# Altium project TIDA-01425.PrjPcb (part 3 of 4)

## Sheet DDR3.schdoc: DDR3
size 431 x 279 mm; Date: Not shown in title block; ApprovedBy: Not shown in title block; CheckedBy: Not shown in title block; Author: Not shown in title block; CompanyName: Not shown in title block; DrawnBy: Donovan Porter; Engineer: Not shown in title block; Organization: Not shown in title block; Address1: Not shown in title block; Address2: Not shown in title block; Address3: Not shown in title block; Address4: Not shown in title block; DocumentNumber: 6; Revision: Use project parameter SCH_Rev; SheetNumber: 6; SheetTotal: 12; PageSetup: Record=PageOptions¦CenterHorizontal=True¦CenterVertical=True¦PrintScale=1.00¦XCorrection=1.00¦YCorrection=1.00¦PrintKind=0¦BorderSize=5000000¦LeftOffset=0¦BottomOffset=0¦Orientation=2¦PaperLength=1000¦PaperWidth=1000¦Scale=100¦PaperSource=15¦PrintQuality=600¦MediaType=1¦DitherType=10¦PaperKind=Letter¦PrintScaleMode=1
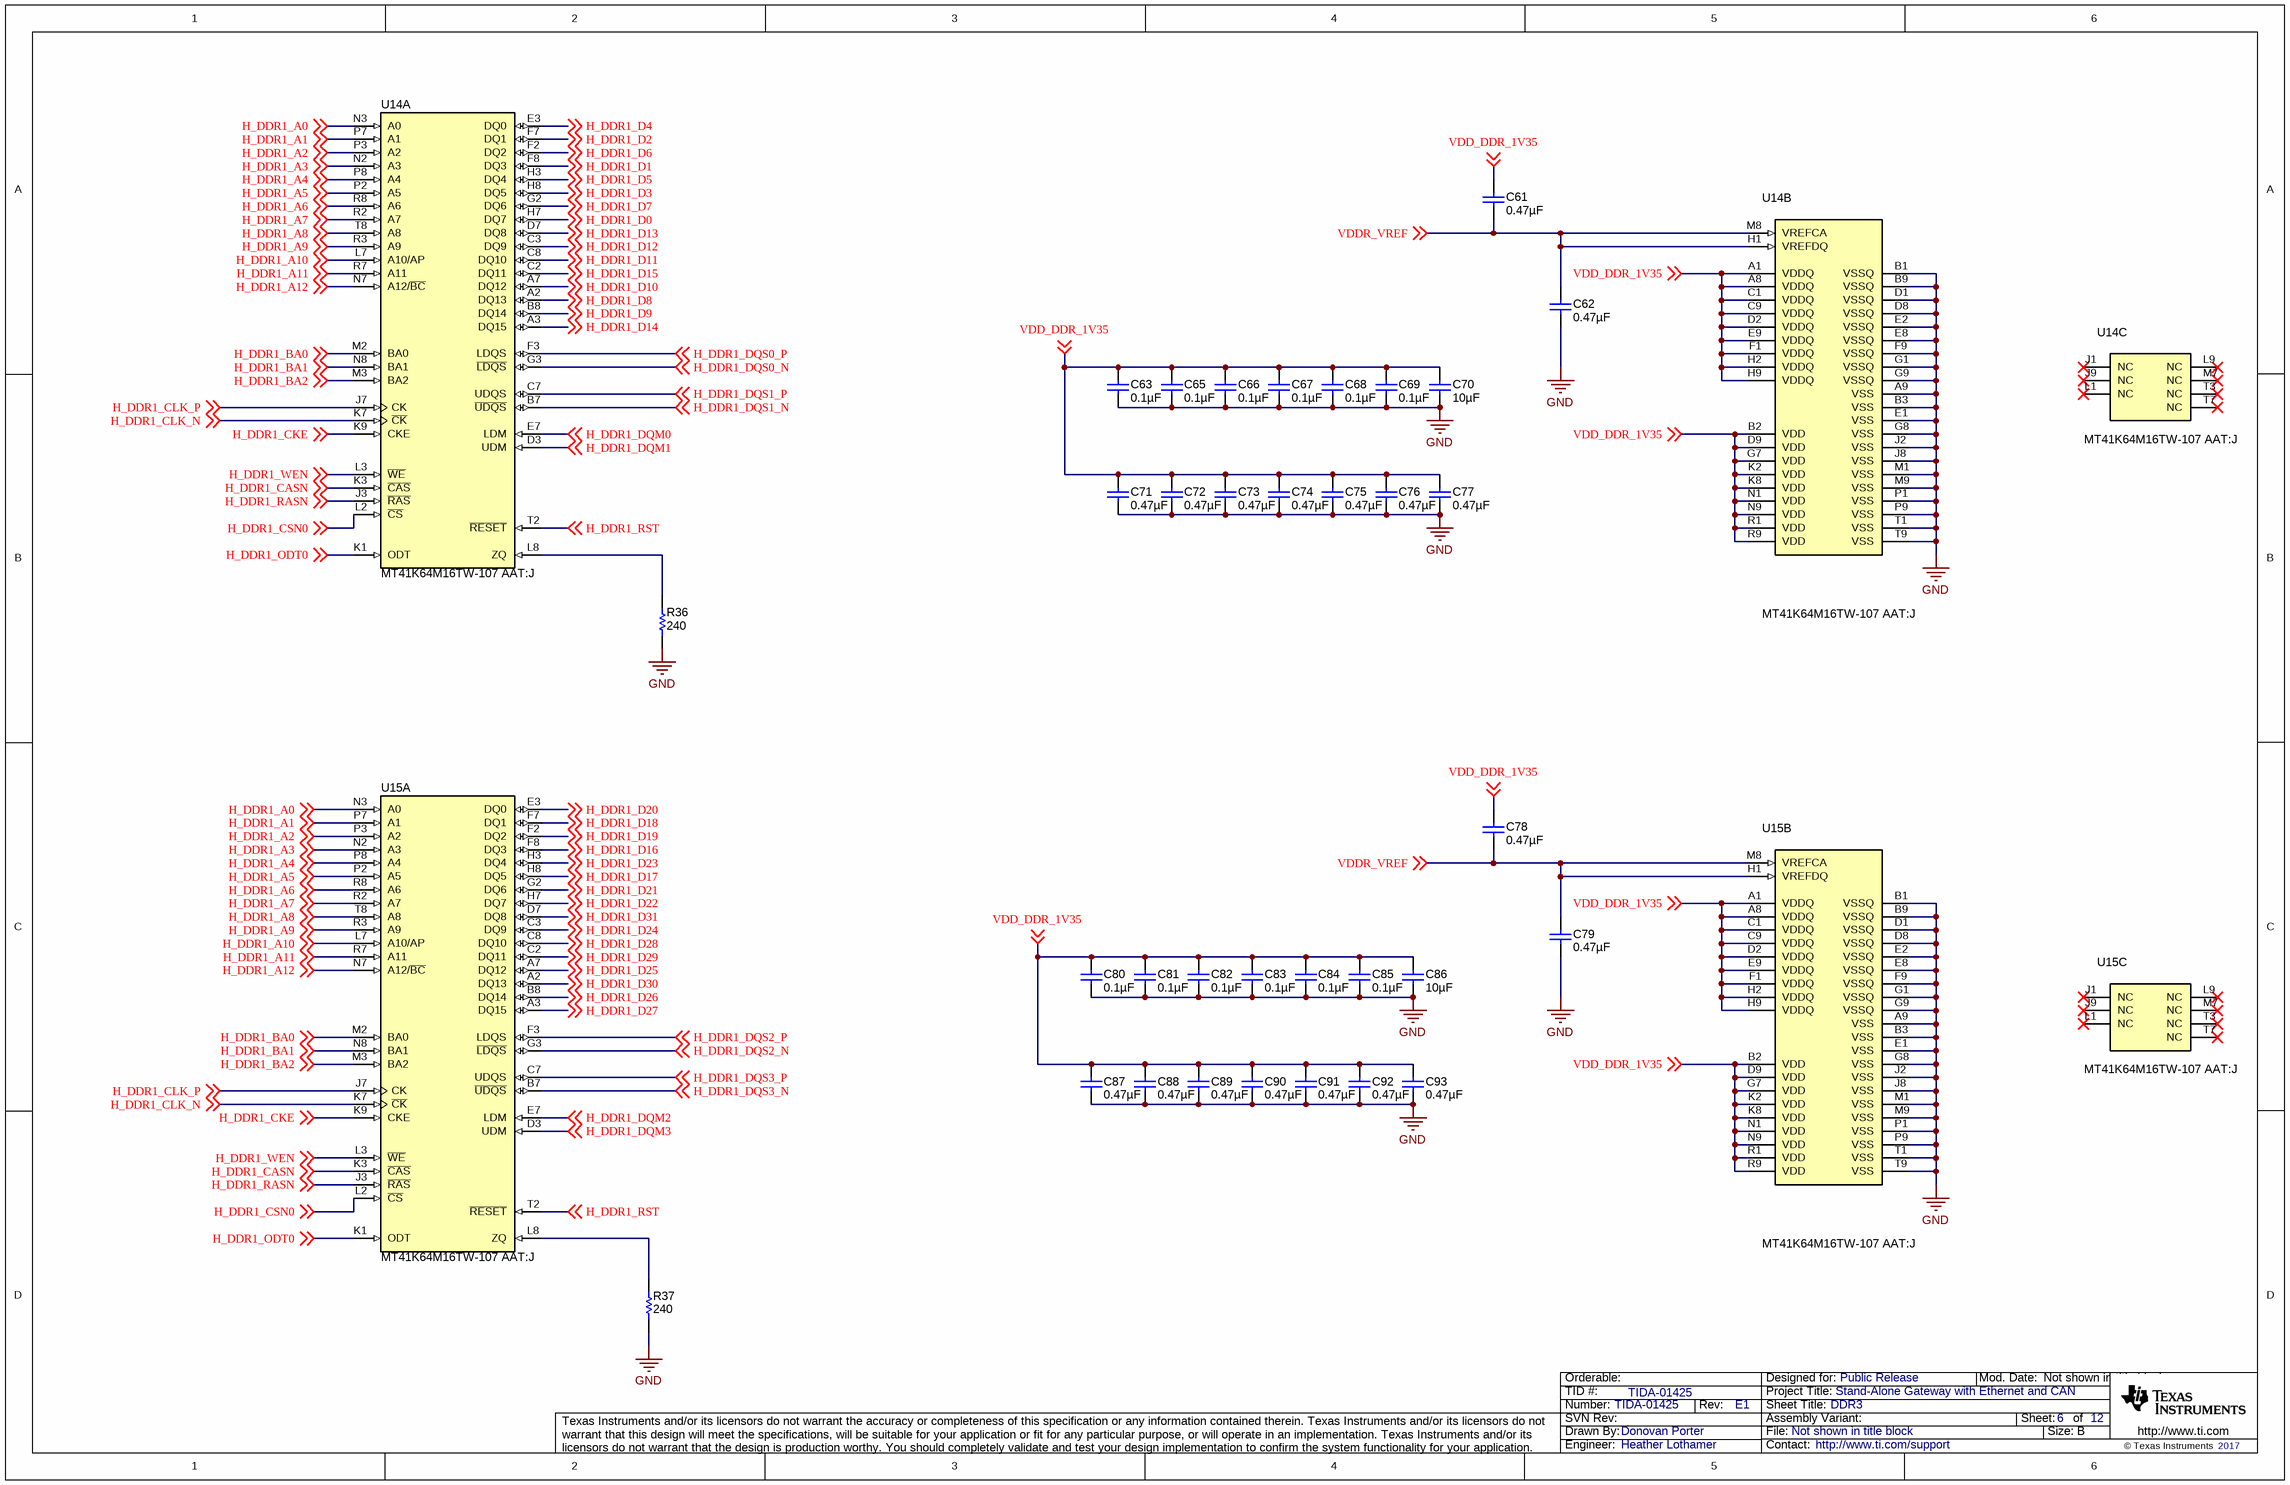
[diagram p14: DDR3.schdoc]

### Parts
C61  ValueDisplayed: 0.47µF  [0402L]  (hidden comment: GCM155C71A474KE36D)
C62  ValueDisplayed: 0.47µF  [0402L]  (hidden comment: GCM155C71A474KE36D)
C63  ValueDisplayed: 0.1µF  [0402L]  (hidden comment: GCM155R71C104KA55D)
C65  ValueDisplayed: 0.1µF  [0402L]  (hidden comment: GCM155R71C104KA55D)
C66  ValueDisplayed: 0.1µF  [0402L]  (hidden comment: GCM155R71C104KA55D)
C67  ValueDisplayed: 0.1µF  [0402L]  (hidden comment: GCM155R71C104KA55D)
C68  ValueDisplayed: 0.1µF  [0402L]  (hidden comment: GCM155R71C104KA55D)
C69  ValueDisplayed: 0.1µF  [0402L]  (hidden comment: GCM155R71C104KA55D)
C70  ValueDisplayed: 10µF  [0805_HV]  (hidden comment: LMK212BJ106KG-T)
C71  ValueDisplayed: 0.47µF  [0402L]  (hidden comment: GCM155C71A474KE36D)
C72  ValueDisplayed: 0.47µF  [0402L]  (hidden comment: GCM155C71A474KE36D)
C73  ValueDisplayed: 0.47µF  [0402L]  (hidden comment: GCM155C71A474KE36D)
C74  ValueDisplayed: 0.47µF  [0402L]  (hidden comment: GCM155C71A474KE36D)
C75  ValueDisplayed: 0.47µF  [0402L]  (hidden comment: GCM155C71A474KE36D)
C76  ValueDisplayed: 0.47µF  [0402L]  (hidden comment: GCM155C71A474KE36D)
C77  ValueDisplayed: 0.47µF  [0402L]  (hidden comment: GCM155C71A474KE36D)
C78  ValueDisplayed: 0.47µF  [0402L]  (hidden comment: GCM155C71A474KE36D)
C79  ValueDisplayed: 0.47µF  [0402L]  (hidden comment: GCM155C71A474KE36D)
C80  ValueDisplayed: 0.1µF  [0402L]  (hidden comment: GCM155R71C104KA55D)
C81  ValueDisplayed: 0.1µF  [0402L]  (hidden comment: GCM155R71C104KA55D)
C82  ValueDisplayed: 0.1µF  [0402L]  (hidden comment: GCM155R71C104KA55D)
C83  ValueDisplayed: 0.1µF  [0402L]  (hidden comment: GCM155R71C104KA55D)
C84  ValueDisplayed: 0.1µF  [0402L]  (hidden comment: GCM155R71C104KA55D)
C85  ValueDisplayed: 0.1µF  [0402L]  (hidden comment: GCM155R71C104KA55D)
C86  ValueDisplayed: 10µF  [0805_HV]  (hidden comment: LMK212BJ106KG-T)
C87  ValueDisplayed: 0.47µF  [0402L]  (hidden comment: GCM155C71A474KE36D)
C88  ValueDisplayed: 0.47µF  [0402L]  (hidden comment: GCM155C71A474KE36D)
C89  ValueDisplayed: 0.47µF  [0402L]  (hidden comment: GCM155C71A474KE36D)
C90  ValueDisplayed: 0.47µF  [0402L]  (hidden comment: GCM155C71A474KE36D)
C91  ValueDisplayed: 0.47µF  [0402L]  (hidden comment: GCM155C71A474KE36D)
C92  ValueDisplayed: 0.47µF  [0402L]  (hidden comment: GCM155C71A474KE36D)
C93  ValueDisplayed: 0.47µF  [0402L]  (hidden comment: GCM155C71A474KE36D)
R36  ValueDisplayed: 240  [0402]  (hidden comment: ERJ-2RKF2400X)
R37  ValueDisplayed: 240  [0402]  (hidden comment: ERJ-2RKF2400X)
U14  MT41K64M16TW-107 AAT:J  [96-FBGA]  (parts A,B,C of 3)
U15  MT41K64M16TW-107 AAT:J  [96-FBGA]  (parts A,B,C of 3)

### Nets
GND: C62.2 C63.2 C65.2 C66.2 C67.2 C68.2 C69.2 C70.2 C71.2 C72.2 C73.2 C74.2 C75.2 C76.2 C77.2 C79.2 C80.2 C81.2 C82.2 C83.2 C84.2 C85.2 C86.2 C87.2 C88.2 C89.2 C90.2 C91.2 C92.2 C93.2 R36.1 R37.1 U14.A9(VSS) U14.B1(VSSQ) U14.B3(VSS) U14.B9(VSSQ) U14.D1(VSSQ) U14.D8(VSSQ) U14.E1(VSS) U14.E2(VSSQ) U14.E8(VSSQ) U14.F9(VSSQ) U14.G1(VSSQ) U14.G8(VSS) U14.G9(VSSQ) U14.J2(VSS) U14.J8(VSS) U14.M1(VSS) U14.M9(VSS) U14.P1(VSS) U14.P9(VSS) U14.T1(VSS) U14.T9(VSS) U15.A9(VSS) U15.B1(VSSQ) U15.B3(VSS) U15.B9(VSSQ) U15.D1(VSSQ) U15.D8(VSSQ) U15.E1(VSS) U15.E2(VSSQ) U15.E8(VSSQ) U15.F9(VSSQ) U15.G1(VSSQ) U15.G8(VSS) U15.G9(VSSQ) U15.J2(VSS) U15.J8(VSS) U15.M1(VSS) U15.M9(VSS) U15.P1(VSS) U15.P9(VSS) U15.T1(VSS) U15.T9(VSS)
H_DDR1_A0: U14.N3(A0) U15.N3(A0) ; off-sheet H_DDR1_A0
H_DDR1_A1: U14.P7(A1) U15.P7(A1) ; off-sheet H_DDR1_A1
H_DDR1_A2: U14.P3(A2) U15.P3(A2) ; off-sheet H_DDR1_A2
H_DDR1_A3: U14.N2(A3) U15.N2(A3) ; off-sheet H_DDR1_A3
H_DDR1_A4: U14.P8(A4) U15.P8(A4) ; off-sheet H_DDR1_A4
H_DDR1_A5: U14.P2(A5) U15.P2(A5) ; off-sheet H_DDR1_A5
H_DDR1_A6: U14.R8(A6) U15.R8(A6) ; off-sheet H_DDR1_A6
H_DDR1_A7: U14.R2(A7) U15.R2(A7) ; off-sheet H_DDR1_A7
H_DDR1_A8: U14.T8(A8) U15.T8(A8) ; off-sheet H_DDR1_A8
H_DDR1_A9: U14.R3(A9) U15.R3(A9) ; off-sheet H_DDR1_A9
H_DDR1_A10: U14.L7(A10/AP) U15.L7(A10/AP) ; off-sheet H_DDR1_A10
H_DDR1_A11: U14.R7(A11) U15.R7(A11) ; off-sheet H_DDR1_A11
H_DDR1_A12: U14.N7(A12/~{BC}) U15.N7(A12/~{BC}) ; off-sheet H_DDR1_A12
H_DDR1_BA0: U14.M2(BA0) U15.M2(BA0) ; off-sheet H_DDR1_BA0
H_DDR1_BA1: U14.N8(BA1) U15.N8(BA1) ; off-sheet H_DDR1_BA1
H_DDR1_BA2: U14.M3(BA2) U15.M3(BA2) ; off-sheet H_DDR1_BA2
H_DDR1_CASN: U14.K3(~{CAS}) U15.K3(~{CAS}) ; off-sheet H_DDR1_CASN
H_DDR1_CKE: U14.K9(CKE) U15.K9(CKE) ; off-sheet H_DDR1_CKE
H_DDR1_CLK_N: U14.K7(~{CK}) U15.K7(~{CK}) ; off-sheet H_DDR1_CLK_N
H_DDR1_CLK_P: U14.J7(CK) U15.J7(CK) ; off-sheet H_DDR1_CLK_P
H_DDR1_CSN0: U14.L2(~{CS}) U15.L2(~{CS}) ; off-sheet H_DDR1_CSN0
H_DDR1_D0: U14.H7(DQ7) ; off-sheet H_DDR1_D0
H_DDR1_D1: U14.F8(DQ3) ; off-sheet H_DDR1_D1
H_DDR1_D2: U14.F7(DQ1) ; off-sheet H_DDR1_D2
H_DDR1_D3: U14.H8(DQ5) ; off-sheet H_DDR1_D3
H_DDR1_D4: U14.E3(DQ0) ; off-sheet H_DDR1_D4
H_DDR1_D5: U14.H3(DQ4) ; off-sheet H_DDR1_D5
H_DDR1_D6: U14.F2(DQ2) ; off-sheet H_DDR1_D6
H_DDR1_D7: U14.G2(DQ6) ; off-sheet H_DDR1_D7
H_DDR1_D8: U14.A2(DQ13) ; off-sheet H_DDR1_D8
H_DDR1_D9: U14.B8(DQ14) ; off-sheet H_DDR1_D9
H_DDR1_D10: U14.A7(DQ12) ; off-sheet H_DDR1_D10
H_DDR1_D11: U14.C8(DQ10) ; off-sheet H_DDR1_D11
H_DDR1_D12: U14.C3(DQ9) ; off-sheet H_DDR1_D12
H_DDR1_D13: U14.D7(DQ8) ; off-sheet H_DDR1_D13
H_DDR1_D14: U14.A3(DQ15) ; off-sheet H_DDR1_D14
H_DDR1_D15: U14.C2(DQ11) ; off-sheet H_DDR1_D15
H_DDR1_D16: U15.F8(DQ3) ; off-sheet H_DDR1_D16
H_DDR1_D17: U15.H8(DQ5) ; off-sheet H_DDR1_D17
H_DDR1_D18: U15.F7(DQ1) ; off-sheet H_DDR1_D18
H_DDR1_D19: U15.F2(DQ2) ; off-sheet H_DDR1_D19
H_DDR1_D20: U15.E3(DQ0) ; off-sheet H_DDR1_D20
H_DDR1_D21: U15.G2(DQ6) ; off-sheet H_DDR1_D21
H_DDR1_D22: U15.H7(DQ7) ; off-sheet H_DDR1_D22
H_DDR1_D23: U15.H3(DQ4) ; off-sheet H_DDR1_D23
H_DDR1_D24: U15.C3(DQ9) ; off-sheet H_DDR1_D24
H_DDR1_D25: U15.A7(DQ12) ; off-sheet H_DDR1_D25
H_DDR1_D26: U15.B8(DQ14) ; off-sheet H_DDR1_D26
H_DDR1_D27: U15.A3(DQ15) ; off-sheet H_DDR1_D27
H_DDR1_D28: U15.C8(DQ10) ; off-sheet H_DDR1_D28
H_DDR1_D29: U15.C2(DQ11) ; off-sheet H_DDR1_D29
H_DDR1_D30: U15.A2(DQ13) ; off-sheet H_DDR1_D30
H_DDR1_D31: U15.D7(DQ8) ; off-sheet H_DDR1_D31
H_DDR1_DQM0: U14.E7(LDM) ; off-sheet H_DDR1_DQM0
H_DDR1_DQM1: U14.D3(UDM) ; off-sheet H_DDR1_DQM1
H_DDR1_DQM2: U15.E7(LDM) ; off-sheet H_DDR1_DQM2
H_DDR1_DQM3: U15.D3(UDM) ; off-sheet H_DDR1_DQM3
H_DDR1_DQS0_N: U14.G3(~{LDQS}) ; off-sheet H_DDR1_DQS0_N
H_DDR1_DQS0_P: U14.F3(LDQS) ; off-sheet H_DDR1_DQS0_P
H_DDR1_DQS1_N: U14.B7(~{UDQS}) ; off-sheet H_DDR1_DQS1_N
H_DDR1_DQS1_P: U14.C7(UDQS) ; off-sheet H_DDR1_DQS1_P
H_DDR1_DQS2_N: U15.G3(~{LDQS}) ; off-sheet H_DDR1_DQS2_N
H_DDR1_DQS2_P: U15.F3(LDQS) ; off-sheet H_DDR1_DQS2_P
H_DDR1_DQS3_N: U15.B7(~{UDQS}) ; off-sheet H_DDR1_DQS3_N
H_DDR1_DQS3_P: U15.C7(UDQS) ; off-sheet H_DDR1_DQS3_P
H_DDR1_ODT0: U14.K1(ODT) U15.K1(ODT) ; off-sheet H_DDR1_ODT0
H_DDR1_RASN: U14.J3(~{RAS}) U15.J3(~{RAS}) ; off-sheet H_DDR1_RASN
H_DDR1_RST: U14.T2(~{RESET}) U15.T2(~{RESET}) ; off-sheet H_DDR1_RST
H_DDR1_WEN: U14.L3(~{WE}) U15.L3(~{WE}) ; off-sheet H_DDR1_WEN
VDD_DDR_1V35: C61.1 C63.1 C65.1 C66.1 C67.1 C68.1 C69.1 C70.1 C71.1 C72.1 C73.1 C74.1 C75.1 C76.1 C77.1 C78.1 C80.1 C81.1 C82.1 C83.1 C84.1 C85.1 C86.1 C87.1 C88.1 C89.1 C90.1 C91.1 C92.1 C93.1 U14.A1(VDDQ) U14.A8(VDDQ) U14.B2(VDD) U14.C1(VDDQ) U14.C9(VDDQ) U14.D2(VDDQ) U14.D9(VDD) U14.E9(VDDQ) U14.F1(VDDQ) U14.G7(VDD) U14.H2(VDDQ) U14.H9(VDDQ) U14.K2(VDD) U14.K8(VDD) U14.N1(VDD) U14.N9(VDD) U14.R1(VDD) U14.R9(VDD) U15.A1(VDDQ) U15.A8(VDDQ) U15.B2(VDD) U15.C1(VDDQ) U15.C9(VDDQ) U15.D2(VDDQ) U15.D9(VDD) U15.E9(VDDQ) U15.F1(VDDQ) U15.G7(VDD) U15.H2(VDDQ) U15.H9(VDDQ) U15.K2(VDD) U15.K8(VDD) U15.N1(VDD) U15.N9(VDD) U15.R1(VDD) U15.R9(VDD) ; off-sheet VDD_DDR_1V35
VDDR_VREF: C61.2 C62.1 C78.2 C79.1 U14.H1(VREFDQ) U14.M8(VREFCA) U15.H1(VREFDQ) U15.M8(VREFCA) ; off-sheet VDDR_VREF
NetR36_2: R36.2 U14.L8(ZQ)
NetR37_2: R37.2 U15.L8(ZQ)

Not connected (* = marked no-connect by the designer): U14 J1(NC)* J9(NC)* L1(NC)* L9(NC)* M7(NC)* T3(NC)* T7(NC)*; U15 J1(NC)* J9(NC)* L1(NC)* L9(NC)* M7(NC)* T3(NC)* T7(NC)*

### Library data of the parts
C61 C62 C71-C79 C87-C93 = GCM155C71A474KE36D: CAP, CERM, 0.47 µF, 10 V, +/- 10%, X7S, 0402; Manufacturer: MuRata; Polarized: N; CompType: Capacitor; Value: 0.47uF; U/M: EA; Cap_F: 0.00000047; Tolerance_%: 10; Value1: Unknown; Value2: 10V; TaMin_C: -55; TaMax_C: 125; Cap_Case: 0402; SizeArea_mm2: 0.5; SizeAreaWB_mm2: 3; SizeX_mm: 1; SizeZ_mm: 0.6; AEC Category: Q200
C63 C65-C69 C80-C85 = GCM155R71C104KA55D: CAP, CERM, 0.1 µF, 16 V, +/- 10%, X7R, 0402; Manufacturer: MuRata; Polarized: N; CompType: Capacitor; Value: 0.1uF; U/M: EA; Cap_F: 0.0000001; Tolerance_%: 10; Value1: Unknown; VDC_V: 16; Value2: 16V; TaMin_C: -55; TaMax_C: 125; Cap_Case: 0402; SizeArea_mm2: 0.5; SizeAreaWB_mm2: 3; SizeX_mm: 1; SizeZ_mm: 0.6; AEC Category: Q200
C70 C86 = LMK212BJ106KG-T: CAP, CERM, 10 µF, 10 V, +/- 10%, X5R, 0805; Manufacturer: Taiyo Yuden; Polarized: N; CompType: Capacitor; Value: 10uF; U/M: EA; Cap_F: 0.00001; Tolerance_%: 10; Value1: Unknown; Value2: 10V; TaMin_C: -55; TaMax_C: 85; Cap_Case: 0805; SizeArea_mm2: 2.5; SizeAreaWB_mm2: 6.75; SizeX_mm: 2; SizeY_mm: 1.25; SizeZ_mm: 1.45; AEC Category: Q200
R36 R37 = ERJ-2RKF2400X: RES, 240, 1%, 0.1 W, AEC-Q200 Grade 0, 0402; Manufacturer: Panasonic; CompType: Resistor; Value: 240; Value_Code: 240R; Tolerance_%: 1; Power_W: 0.1; Value2: 0.1W; VDC_V: 50; TempCo: 100 ppm/C; SizeArea_mm2: 0.5; SizeZ_mm: 0.6; U/M: EA; AEC Category: Q200; AEC Qualified: Y; AEC Grade: 0
U14 U15 = MT41K64M16TW-107 AAT:J: SDRAM 1GBIT 933MHZ 96FBGA; Manufacturer: Micron Technology; SymbolCreator: Altium

## Sheet Ethernet_subsystem.SchDoc: Ethernet_subsystem
size 431 x 279 mm; Date: Not shown in title block; ApprovedBy: Not shown in title block; CheckedBy: Not shown in title block; Author: Not shown in title block; CompanyName: Not shown in title block; DrawnBy: Donovan Porter; Engineer: Not shown in title block; Organization: Not shown in title block; Address1: Not shown in title block; Address2: Not shown in title block; Address3: Not shown in title block; Address4: Not shown in title block; DocumentNumber: 4; Revision: Use project parameter SCH_Rev; SheetNumber: 4; SheetTotal: 12; PageSetup: Record=PageOptions¦CenterHorizontal=True¦CenterVertical=True¦PrintScale=1.00¦XCorrection=1.00¦YCorrection=1.00¦PrintKind=0¦BorderSize=5000000¦LeftOffset=0¦BottomOffset=0¦Orientation=2¦PaperLength=1000¦PaperWidth=1000¦Scale=100¦PaperSource=15¦PrintQuality=600¦MediaType=1¦DitherType=10¦PaperKind=Letter¦PrintScaleMode=1
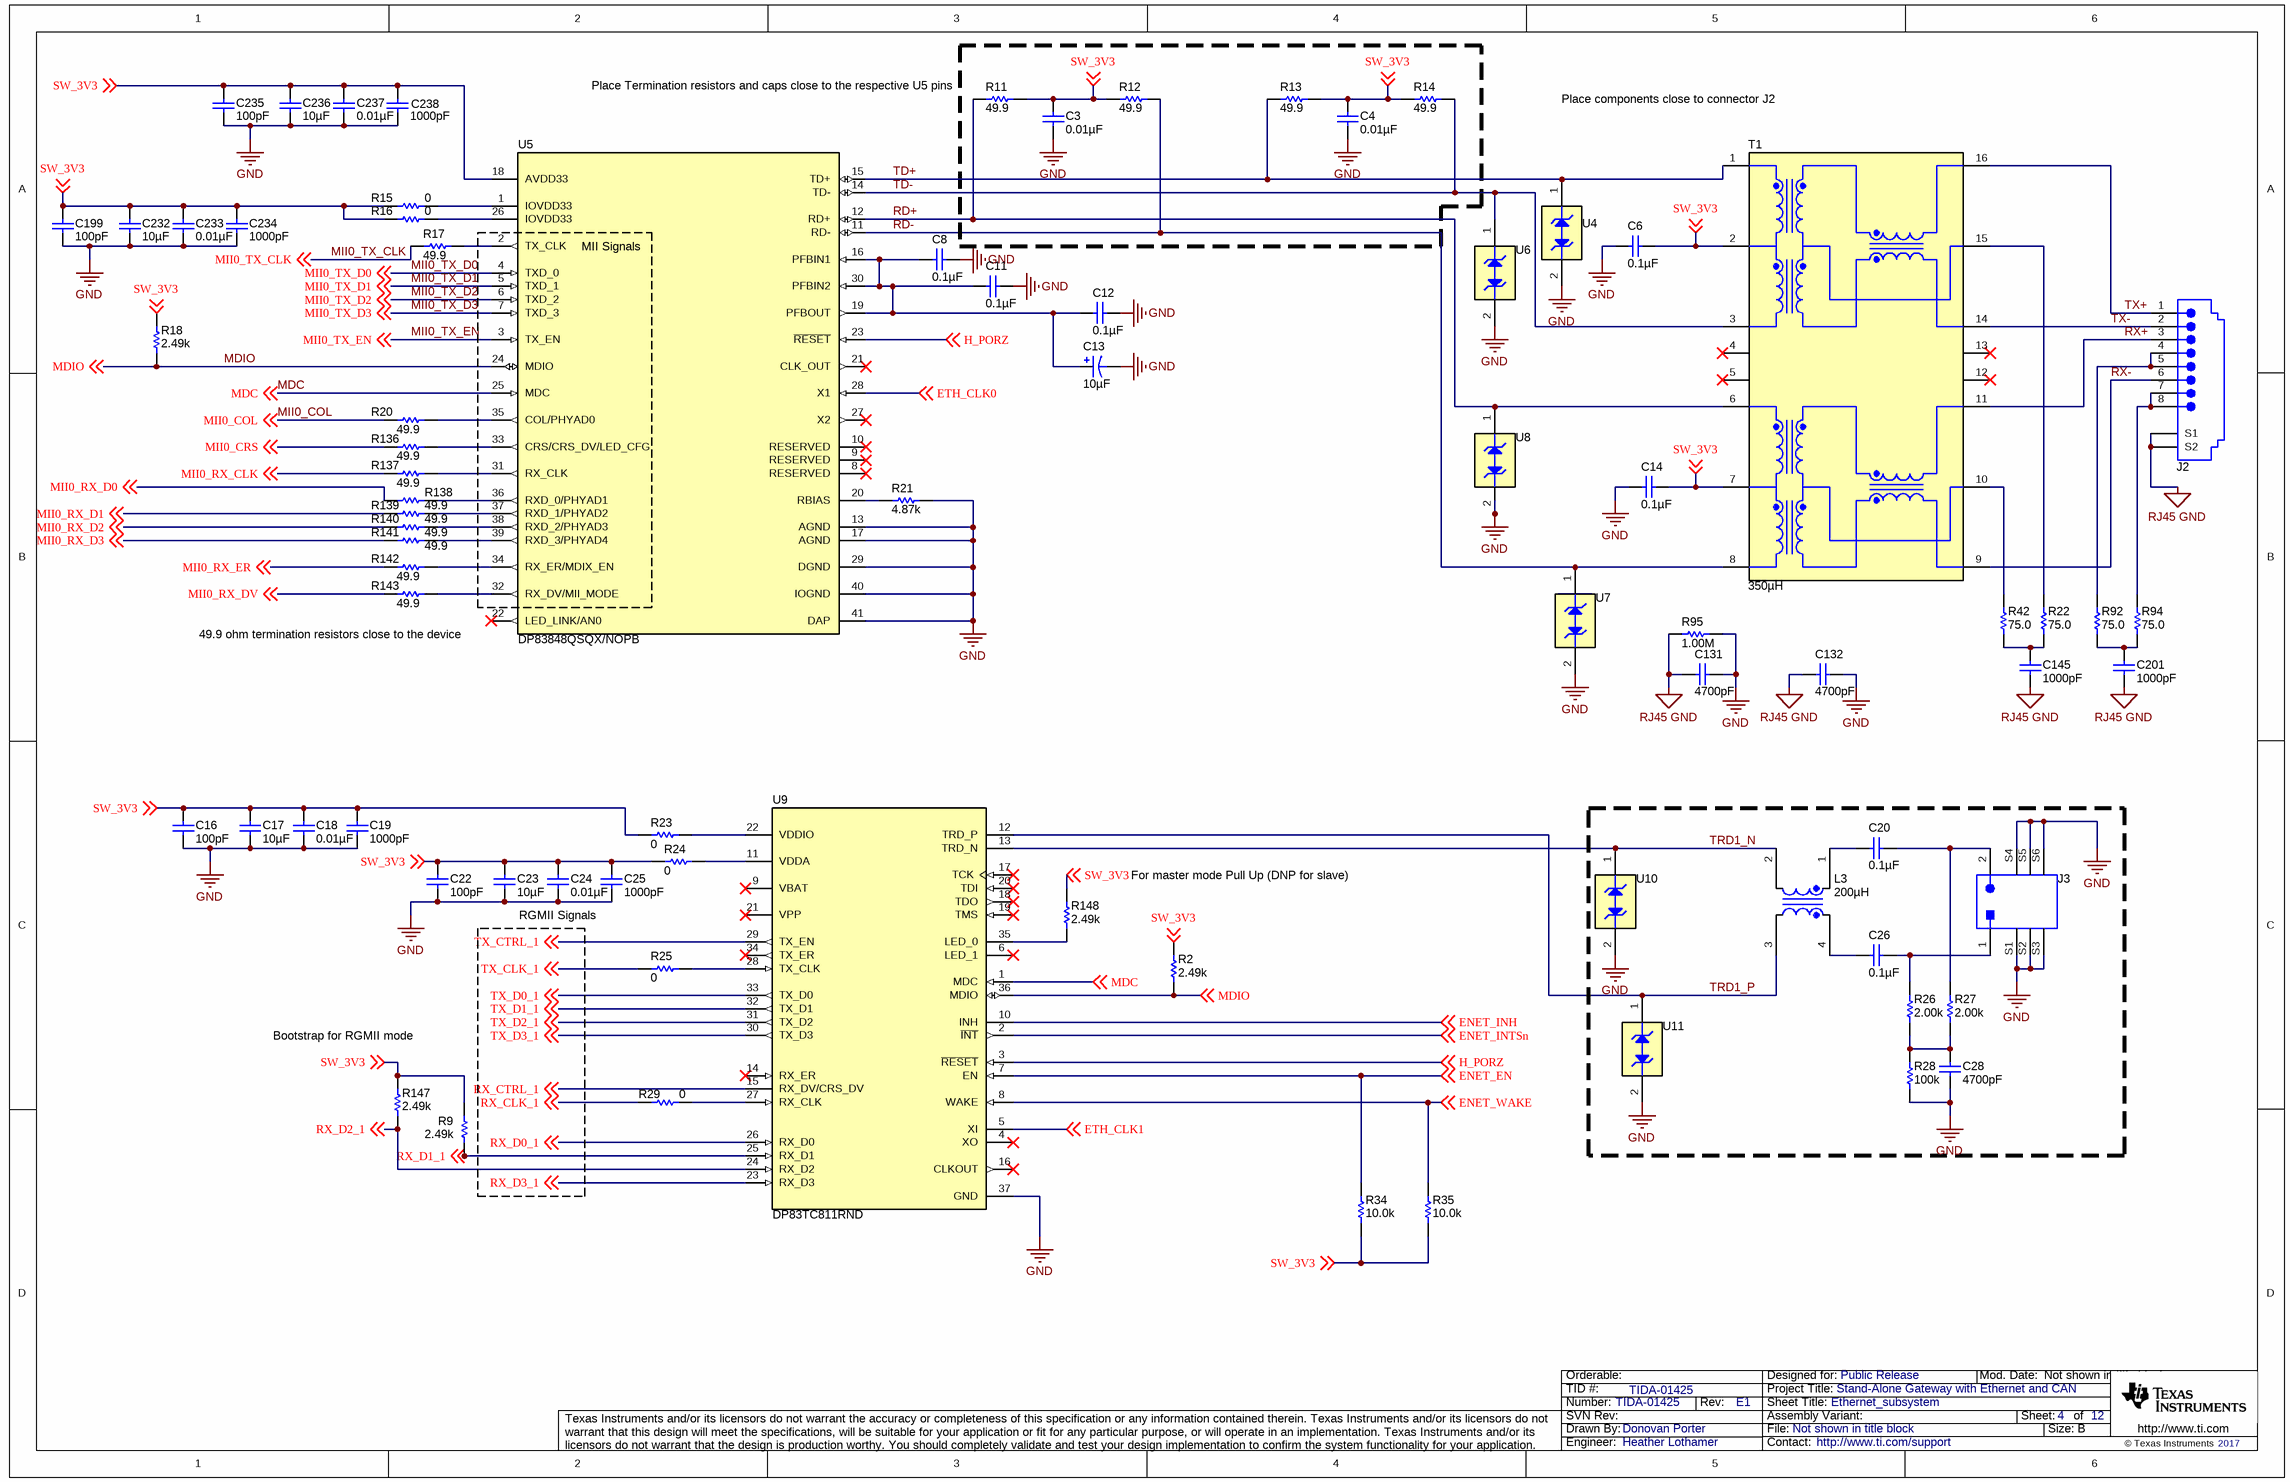
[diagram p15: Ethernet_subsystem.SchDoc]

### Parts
C3  ValueDisplayed: 0.01µF  [0402L]  (hidden comment: 0402ZC103KAT2A)
C4  ValueDisplayed: 0.01µF  [0402L]  (hidden comment: 0402ZC103KAT2A)
C6  ValueDisplayed: 0.1µF  [0805_150]  (hidden comment: CEU4J2X7R1H104K125AE)
C8  ValueDisplayed: 0.1µF  [0402L]  (hidden comment: C0402C104K4RACAUTO)
C11  ValueDisplayed: 0.1µF  [0402L]  (hidden comment: C0402C104K4RACAUTO)
C12  ValueDisplayed: 0.1µF  [0402L]  (hidden comment: C0402C104K4RACAUTO)
C13  ValueDisplayed: 10µF  [6032-28]  (hidden comment: 293D106X9010C2TE3)
C14  ValueDisplayed: 0.1µF  [0805_150]  (hidden comment: CEU4J2X7R1H104K125AE)
C16  ValueDisplayed: 100pF  [0402]  (hidden comment: CGA2B2C0G1H101J050BA)
C17  ValueDisplayed: 10µF  [1210_280]  (hidden comment: CGA6P1X7R1E106M250AC)
C18  ValueDisplayed: 0.01µF  [0402]  (hidden comment: CGA2B3X7R1H103K050BB)
C19  ValueDisplayed: 1000pF  [0402]  (hidden comment: CGA2B2C0G1H102J050BA)
C20  ValueDisplayed: 0.1µF  [0603]  (hidden comment: 06035C104KAT2A)
C22  ValueDisplayed: 100pF  [0402]  (hidden comment: CGA2B2C0G1H101J050BA)
C23  ValueDisplayed: 10µF  [1210_280]  (hidden comment: CGA6P1X7R1E106M250AC)
C24  ValueDisplayed: 0.01µF  [0402]  (hidden comment: CGA2B3X7R1H103K050BB)
C25  ValueDisplayed: 1000pF  [0402]  (hidden comment: CGA2B2C0G1H102J050BA)
C26  ValueDisplayed: 0.1µF  [0603]  (hidden comment: 06035C104KAT2A)
C28  ValueDisplayed: 4700pF  [0603]  (hidden comment: C0603C472K5RACTU)
C131  ValueDisplayed: 4700pF  [0805_HV]  (hidden comment: 08055C472JAT2A)
C132  ValueDisplayed: 4700pF  [0805_HV]  (hidden comment: 08055C472JAT2A)
C145  ValueDisplayed: 1000pF  [1812_254]  (hidden comment: 1812GC102KA1)
C199  ValueDisplayed: 100pF  [0402L]  (hidden comment: CGA2B2C0G1H101J050BA)
C201  ValueDisplayed: 1000pF  [1812_254]  (hidden comment: 1812GC102KA1)
C232  ValueDisplayed: 10µF  [1210_280]  (hidden comment: CGA6P1X7R1E106M250AC)
C233  ValueDisplayed: 0.01µF  [0402L]  (hidden comment: CGA2B3X7R1H103K050BB)
C234  ValueDisplayed: 1000pF  [0402L]  (hidden comment: CGA2B2C0G1H102J050BA)
C235  ValueDisplayed: 100pF  [0402L]  (hidden comment: CGA2B2C0G1H101J050BA)
C236  ValueDisplayed: 10µF  [1210_280]  (hidden comment: CGA6P1X7R1E106M250AC)
C237  ValueDisplayed: 0.01µF  [0402L]  (hidden comment: CGA2B3X7R1H103K050BB)
C238  ValueDisplayed: 1000pF  [0402L]  (hidden comment: CGA2B2C0G1H102J050BA)
J2  ARJ012-110553  [Abracon_ARJ012-110553]  (value not drawn)
J3  0-2290024-1  [TE_1PORT_B1-B]  (value not drawn)
L3  ValueDisplayed: 200µH  [MuRata_DLW43MH]  (hidden comment: DLW43MH201XK2L)
R2  ValueDisplayed: 2.49k  [0201]  (hidden comment: RC0201FR-072K49L)
R9  ValueDisplayed: 2.49k  [0201]  (hidden comment: RC0201FR-072K49L)
R11  ValueDisplayed: 49.9  [0603L]  (hidden comment: CRCW060349R9FKEA)
R12  ValueDisplayed: 49.9  [0603L]  (hidden comment: CRCW060349R9FKEA)
R13  ValueDisplayed: 49.9  [0603L]  (hidden comment: CRCW060349R9FKEA)
R14  ValueDisplayed: 49.9  [0603L]  (hidden comment: CRCW060349R9FKEA)
R15  ValueDisplayed: 0  [0201]  (hidden comment: CRCW02010000Z0ED)
R16  ValueDisplayed: 0  [0201]  (hidden comment: CRCW02010000Z0ED)
R17  ValueDisplayed: 49.9  [0603L]  (hidden comment: CRCW060349R9FKEA)
R18  ValueDisplayed: 2.49k  [0201]  (hidden comment: RC0201FR-072K49L)
R20  ValueDisplayed: 49.9  [0603L]  (hidden comment: CRCW060349R9FKEA)
R21  ValueDisplayed: 4.87k  [0201]  (hidden comment: RC0201FR-074K87L)
R22  ValueDisplayed: 75.0  [0402]  (hidden comment: CRCW040275R0FKED)
R23  ValueDisplayed: 0  [0402L]  (hidden comment: CRCW04020000Z0ED)
R24  ValueDisplayed: 0  [0402L]  (hidden comment: CRCW04020000Z0ED)
R25  ValueDisplayed: 0  [0201]  (hidden comment: CRCW02010000Z0ED)
R26  ValueDisplayed: 2.00k  [0402]  (hidden comment: ERJ-2RKF2001X)
R27  ValueDisplayed: 2.00k  [0402]  (hidden comment: ERJ-2RKF2001X)
R28  ValueDisplayed: 100k  [0402]  (hidden comment: CRCW0402100KFKED)
R29  ValueDisplayed: 0  [0201]  (hidden comment: CRCW02010000Z0ED)
R34  ValueDisplayed: 10.0k  [0603]  (hidden comment: RCG060310K0FKEA)
R35  ValueDisplayed: 10.0k  [0603]  (hidden comment: RCG060310K0FKEA)
R42  ValueDisplayed: 75.0  [0402]  (hidden comment: CRCW040275R0FKED)
R92  ValueDisplayed: 75.0  [0402]  (hidden comment: CRCW040275R0FKED)
R94  ValueDisplayed: 75.0  [0402]  (hidden comment: CRCW040275R0FKED)
R95  ValueDisplayed: 1.00M  [1206]  (hidden comment: RC1206FR-071ML)
R136  ValueDisplayed: 49.9  [0603L]  (hidden comment: CRCW060349R9FKEA)
R137  ValueDisplayed: 49.9  [0603L]  (hidden comment: CRCW060349R9FKEA)
R138  ValueDisplayed: 49.9  [0603L]  (hidden comment: CRCW060349R9FKEA)
R139  ValueDisplayed: 49.9  [0603L]  (hidden comment: CRCW060349R9FKEA)
R140  ValueDisplayed: 49.9  [0603L]  (hidden comment: CRCW060349R9FKEA)
R141  ValueDisplayed: 49.9  [0603L]  (hidden comment: CRCW060349R9FKEA)
R142  ValueDisplayed: 49.9  [0603L]  (hidden comment: CRCW060349R9FKEA)
R143  ValueDisplayed: 49.9  [0603L]  (hidden comment: CRCW060349R9FKEA)
R147  ValueDisplayed: 2.49k  [0402]  (hidden comment: CRCW04022K49FKED)
R148  ValueDisplayed: 2.49k  [0603]  (hidden comment: CRCW06032K49FKEA)
T1  ValueDisplayed: 350µH  [Pulse_HX1188FNLT]  (hidden comment: HX1188FNLT)
U4  TPD1E10B06QDPYRQ1  [DPY0002A]  (value not drawn)
U5  DP83848QSQX/NOPB  [RTA0040A]
U6  TPD1E10B06QDPYRQ1  [DPY0002A]  (value not drawn)
U7  TPD1E10B06QDPYRQ1  [DPY0002A]  (value not drawn)
U8  TPD1E10B06QDPYRQ1  [DPY0002A]  (value not drawn)
U9  DP83TC811RND  [RND0036A]
U10  TPD1E10B06QDPYRQ1  [DPY0002A]  (value not drawn)
U11  TPD1E10B06QDPYRQ1  [DPY0002A]  (value not drawn)

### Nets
GND: C3.2 C4.2 C6.2 C8.1 C11.1 C12.1 C13.2(-) C14.1 C16.2 C17.2 C18.2 C19.2 C22.2 C23.2 C24.2 C25.2 C28.2 C131.1 C132.1 C199.2 C232.2 C233.2 C234.2 C235.2 C236.2 C237.2 C238.2 J3.S1(GND) J3.S2(GND) J3.S3(GND) J3.S4(GND) J3.S5(GND) J3.S6(GND) R21.2 R28.1 R95.2 U4.2(A) U5.13(AGND) U5.17(AGND) U5.29(DGND) U5.40(IOGND) U5.41(DAP) U6.2(A) U7.2(A) U8.2(A) U9.37(GND) U10.2(A) U11.2(A)
RJ45 GND: C131.2 C132.2 C145.2 C201.2 J2.S1 J2.S2 R95.1
ENET_EN: R34.2 U9.7(EN) ; off-sheet ENET_EN
ENET_INH: U9.10(INH) ; off-sheet ENET_INH
ENET_INTSn: U9.2(~{INT}) ; off-sheet ENET_INTSn
ENET_WAKE: R35.2 U9.8(WAKE) ; off-sheet ENET_WAKE
ETH_CLK0: U5.28(X1) ; off-sheet ETH_CLK0
ETH_CLK1: U9.5(XI) ; off-sheet ETH_CLK1
H_PORZ: U5.23(~{RESET}) U9.3(~{RESET}) ; off-sheet H_PORZ
MDC: U5.25(MDC) U9.1(MDC) ; off-sheet MDC
MDIO: R2.1 R18.1 U5.24(MDIO) U9.36(MDIO) ; off-sheet MDIO
MII0_COL: R20.1 ; off-sheet MII0_COL
MII0_CRS: R136.1 ; off-sheet MII0_CRS
MII0_RX_CLK: R137.1 ; off-sheet MII0_RX_CLK
MII0_RX_D0: R138.1 ; off-sheet MII0_RX_D0
MII0_RX_D1: R139.1 ; off-sheet MII0_RX_D1
MII0_RX_D2: R140.1 ; off-sheet MII0_RX_D2
MII0_RX_D3: R141.1 ; off-sheet MII0_RX_D3
MII0_RX_DV: R143.1 ; off-sheet MII0_RX_DV
MII0_RX_ER: R142.1 ; off-sheet MII0_RX_ER
MII0_TX_CLK: R17.1 ; off-sheet MII0_TX_CLK
MII0_TX_D0: U5.4(TXD_0) ; off-sheet MII0_TX_D0
MII0_TX_D1: U5.5(TXD_1) ; off-sheet MII0_TX_D1
MII0_TX_D2: U5.6(TXD_2) ; off-sheet MII0_TX_D2
MII0_TX_D3: U5.7(TXD_3) ; off-sheet MII0_TX_D3
MII0_TX_EN: U5.3(TX_EN) ; off-sheet MII0_TX_EN
RD+: R11.1 T1.6(RD+) U5.12(RD+) U8.1(K)
RD-: R12.2 T1.8(RD-) U5.11(RD-) U7.1(K)
RX+: J2.3 T1.11(RX+)
RX-: J2.6 T1.9(RX-)
RX_CLK_1: R29.1 ; off-sheet RX_CLK_1
RX_CTRL_1: U9.15(RX_DV/CRS_DV) ; off-sheet RX_CTRL_1
RX_D0_1: U9.26(RX_D0) ; off-sheet RX_D0_1
RX_D1_1: R9.1 U9.25(RX_D1) ; off-sheet RX_D1_1
RX_D2_1: R147.1 U9.24(RX_D2) ; off-sheet RX_D2_1
RX_D3_1: U9.23(RX_D3) ; off-sheet RX_D3_1
SW_3V3: C3.1 C4.1 C6.1 C14.2 C16.1 C17.1 C18.1 C19.1 C22.1 C23.1 C24.1 C25.1 C199.1 C232.1 C233.1 C234.1 C235.1 C236.1 C237.1 C238.1 R2.2 R9.2 R11.2 R12.1 R13.2 R14.1 R15.1 R16.1 R18.2 R23.1 R24.1 R34.1 R35.1 R147.2 R148.2 T1.2(TCT) T1.7(RCT) U5.18(AVDD33) ; off-sheet SW_3V3
TD+: R13.1 T1.1(TD+) U4.1(K) U5.15(TD+)
TD-: R14.2 T1.3(TD-) U5.14(TD-) U6.1(K)
TRD1_N: L3.2 U9.13(TRD_N) U10.1(K)
TRD1_P: L3.3 U9.12(TRD_P) U11.1(K)
TX+: J2.1 T1.16(TX+)
TX-: J2.2 T1.14(TX-)
TX_CLK_1: R25.1 ; off-sheet TX_CLK_1
TX_CTRL_1: U9.29(TX_EN) ; off-sheet TX_CTRL_1
TX_D0_1: U9.33(TX_D0) ; off-sheet TX_D0_1
TX_D1_1: U9.32(TX_D1) ; off-sheet TX_D1_1
TX_D2_1: U9.31(TX_D2) ; off-sheet TX_D2_1
TX_D3_1: U9.30(TX_D3) ; off-sheet TX_D3_1
NetC8_2: C8.2 C11.2 C12.2 C13.1(+) U5.16(PFBIN1) U5.19(PFBOUT) U5.30(PFBIN2)
NetC20_1: C20.1 J3.2 R27.2
NetC20_2: C20.2 L3.1
NetC26_1: C26.1 J3.1 R26.2
NetC26_2: C26.2 L3.4
NetC28_1: C28.1 R26.1 R27.1 R28.2
NetC145_1: C145.1 R22.1 R42.1
NetC201_1: C201.1 R92.1 R94.1
NetJ2_4: J2.4 J2.5 R92.2
NetJ2_7: J2.7 J2.8 R94.2
NetR15_2: R15.2 U5.1(IOVDD33)
NetR16_2: R16.2 U5.26(IOVDD33)
NetR17_2: R17.2 U5.2(TX_CLK)
NetR20_2: R20.2 U5.35(COL/PHYAD0)
NetR21_1: R21.1 U5.20(RBIAS)
NetR22_2: R22.2 T1.15(CMT)
NetR23_2: R23.2 U9.22(VDDIO)
NetR24_2: R24.2 U9.11(VDDA)
NetR25_2: R25.2 U9.28(TX_CLK)
NetR29_2: R29.2 U9.27(RX_CLK)
NetR42_2: R42.2 T1.10(CMT)
NetR136_2: R136.2 U5.33(CRS/CRS_DV/LED_CFG)
NetR137_2: R137.2 U5.31(RX_CLK)
NetR138_2: R138.2 U5.36(RXD_0/PHYAD1)
NetR139_2: R139.2 U5.37(RXD_1/PHYAD2)
NetR140_2: R140.2 U5.38(RXD_2/PHYAD3)
NetR141_2: R141.2 U5.39(RXD_3/PHYAD4)
NetR142_2: R142.2 U5.34(RX_ER/MDIX_EN)
NetR143_2: R143.2 U5.32(RX_DV/MII_MODE)
NetR148_1: R148.1 U9.35(LED_0)

Not connected (* = marked no-connect by the designer): T1 4(NC)* 5(NC)* 12(NC)* 13(NC)*; U5 8(RESERVED)* 9(RESERVED)* 10(RESERVED)* 21(CLK_OUT)* 22(LED_LINK/AN0)* 27(X2)*; U9 4(XO)* 6(LED_1)* 9(VBAT)* 14(RX_ER)* 16(CLKOUT)* 17(TCK)* 18(TDO)* 19(TMS)* 20(TDI)* 21(VPP)* 34(TX_ER)*

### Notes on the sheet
- (near R11) Place Termination resistors and caps close to the respective U5 pins
- Place components close to connector J2
- (near U5) MII Signals
- 49.9 ohm termination resistors close to the device
- For master mode Pull Up (DNP for slave)
- RGMII Signals
- (near R147) Bootstrap for RGMII mode

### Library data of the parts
C3 C4 = 0402ZC103KAT2A: CAP, CERM, 0.01 µF, 10 V, +/- 10%, X7R, 0402; Manufacturer: AVX; Polarized: N; CompType: Capacitor; Value: 0.01uF; U/M: EA; Cap_F: 0.00000001; Tolerance_%: 10; Value1: Unknown; Value2: 10V; TaMin_C: -55; TaMax_C: 125; Cap_Case: 0402; SizeArea_mm2: 0.5; SizeAreaWB_mm2: 3; SizeX_mm: 1; SizeZ_mm: 0.6; AEC Category: Q200
C6 C14 = CEU4J2X7R1H104K125AE: CAP, CERM, 0.1 µF, 50 V, +/- 10%, X7R, AEC-Q200 Grade 1, 0805; Manufacturer: TDK; Polarized: N; CompType: Capacitor; Value: 0.1uF; U/M: EA; Cap_F: 0.0000001; Tolerance_%: 10; Value1: Unknown; VDC_V: 50; Value2: 50V; TaMin_C: -55; TaMax_C: 125; Cap_Case: 0805; SizeArea_mm2: 2.5; SizeAreaWB_mm2: 6.75; SizeX_mm: 2; SizeY_mm: 1.25; SizeZ_mm: 1.5; AEC Category: Q200; AEC Qualified: Y; AEC Grade: 1
C8 C11 C12 = C0402C104K4RACAUTO: CAP, CERM, 0.1 µF, 16 V, +/- 10%, X7R, AEC-Q200 Grade 1, 0402; Manufacturer: Kemet; Polarized: N; CompType: Capacitor; Value: 0.1uF; U/M: EA; Cap_F: 0.0000001; Tolerance_%: 10; Value1: Unknown; VDC_V: 16; Value2: 16V; TaMin_C: -55; TaMax_C: 125; Cap_Case: 0402; SizeArea_mm2: 0.5; SizeAreaWB_mm2: 3; SizeX_mm: 1; SizeZ_mm: 0.6; AEC Category: Q200; AEC Qualified: Y
C13 = 293D106X9010C2TE3: CAP, TA, 10 µF, 10 V, +/- 10%, 1.8 ohm, SMD; Manufacturer: Vishay-Sprague; Polarized: Y; CompType: Capacitor; Value: 10uF; U/M: EA; Cap_F: 0.00001; Tolerance_%: 10; Value1: 1.8 ohm; Value2: 10V; ESR_ohm: 1.8; IRMS_A: 0.25; TaMin_C: -55; TaMax_C: 125; Cap_Case: C; SizeAreaWB_mm2: 41.6; SizeArea_mm2: 19.2; SizeX_mm: 6; SizeY_mm: 3.2; SizeZ_mm: 2.8; AEC Category: Q200
C16 C22 = CGA2B2C0G1H101J050BA: CAP, CERM, 100 pF, 50 V, +/- 5%, C0G/NP0, AEC-Q200 Grade 1, 0402; Manufacturer: TDK; Polarized: N; CompType: Capacitor; Value: 100pF; U/M: EA; Cap_F: 0.0000000001; Tolerance_%: 5; Value1: Unknown; VDC_V: 50; Value2: 50V; TaMin_C: -55; TaMax_C: 125; AEC Category: Q200; AEC Qualified: Y; AEC Grade: 1
C17 C23 C232 C236 = CGA6P1X7R1E106M250AC: CAP, CERM, 10 µF, 25 V, +/- 20%, X7R, AEC-Q200 Grade 1, 1210; Manufacturer: TDK; Polarized: N; CompType: Capacitor; Value: 10uF; U/M: EA; Cap_F: 0.00001; Tolerance_%: 20; Value1: Unknown; VDC_V: 25; Value2: 25V; TaMin_C: -55; TaMax_C: 125; Cap_Case: 1210; AEC Category: Q200; AEC Qualified: Y; AEC Grade: 1
C18 C24 = CGA2B3X7R1H103K050BB: CAP, CERM, 0.01 µF, 50 V, +/- 10%, X7R, AEC-Q200 Grade 1, 0402; Manufacturer: TDK; Polarized: N; CompType: Capacitor; Value: 0.01uF; U/M: EA; Cap_F: 0.00000001; Tolerance_%: 10; Value1: Unknown; VDC_V: 50; Value2: 50V; TaMin_C: -55; TaMax_C: 125; AEC Category: Q200; AEC Qualified: Y; AEC Grade: 1
C19 C25 = CGA2B2C0G1H102J050BA: CAP, CERM, 1000 pF, 50 V, +/- 5%, C0G/NP0, AEC-Q200 Grade 1, 0402; Manufacturer: TDK; Polarized: N; CompType: Capacitor; Value: 1000pF; U/M: EA; Cap_F: 0.000000001; Tolerance_%: 5; Value1: Unknown; VDC_V: 50; Value2: 50V; TaMin_C: -55; TaMax_C: 125; AEC Category: Q200; AEC Qualified: Y; AEC Grade: 1
C20 C26 = 06035C104KAT2A: CAP, CERM, 0.1 µF, 50 V, +/- 10%, X7R, 0603; Manufacturer: AVX; Polarized: N; CompType: Capacitor; Value: 0.1uF; U/M: EA; Cap_F: 0.0000001; Tolerance_%: 10; Value1: Unknown; VDC_V: 50; Value2: 50V; TaMin_C: -55; TaMax_C: 125; SizeArea_mm2: 1.28; SizeAreaWB_mm2: 4.68; SizeX_mm: 1.6; SizeY_mm: 0.8; SizeZ_mm: 1; AEC Category: Q200
C28 = C0603C472K5RACTU: CAP, CERM, 4700 pF, 50 V, +/- 10%, X7R, 0603; Manufacturer: Kemet; Polarized: N; CompType: Capacitor; Value: 4700pF; U/M: EA; Cap_F: 0.0000000047; Tolerance_%: 10; Value1: Unknown; VDC_V: 50; Value2: 50V; TaMin_C: -55; TaMax_C: 125; SizeArea_mm2: 1.28; SizeAreaWB_mm2: 4.68; SizeX_mm: 1.6; SizeY_mm: 0.8; SizeZ_mm: 1; AEC Category: Q200
C131 C132 = 08055C472JAT2A: CAP, CERM, 4700 pF, 50 V, +/- 5%, X7R, 0805; Manufacturer: AVX; Polarized: N; CompType: Capacitor; Value: 4700pF; U/M: EA; Cap_F: 0.0000000047; Tolerance_%: 5; ESR_ohm: 0.119; Value1: 0.119 ohm; VDC_V: 50; Value2: 50V; TaMin_C: -55; TaMax_C: 125; Cap_Case: 0805; SizeArea_mm2: 2.5; SizeAreaWB_mm2: 6.75; SizeX_mm: 2; SizeY_mm: 1.25; SizeZ_mm: 1.45; AEC Category: Q200
C145 C201 = 1812GC102KA1: CAP, CERM, 1000 pF, 2000 V, +/- 10%, X7R, 1812; Manufacturer: AVX; Polarized: N; CompType: Capacitor; Value: 1000pF; U/M: EA; Cap_F: 0.000000001; Tolerance_%: 10; Value1: Unknown; VDC_V: 2000; Value2: 2000V; TaMin_C: -55; TaMax_C: 125; Cap_Case: 1812; SizeArea_mm2: 14.4; SizeAreaWB_mm2: 23.1; SizeX_mm: 4.5; SizeY_mm: 3.2; SizeZ_mm: 2.54; AEC Category: Q200
C199 C235 = CGA2B2C0G1H101J050BA: CAP, CERM, 100 pF, 50 V, +/- 5%, C0G/NP0, AEC-Q200 Grade 1, 0402; Manufacturer: TDK; Polarized: N; CompType: Capacitor; Value: 100pF; U/M: EA; Cap_F: 0.0000000001; Tolerance_%: 5; Value1: Unknown; VDC_V: 50; Value2: 50V; TaMin_C: -55; TaMax_C: 125; Cap_Case: 0402; AEC Category: Q200; AEC Qualified: Y; AEC Grade: 1
C233 C237 = CGA2B3X7R1H103K050BB: CAP, CERM, 0.01 µF, 50 V, +/- 10%, X7R, AEC-Q200 Grade 1, 0402; Manufacturer: TDK; Polarized: N; CompType: Capacitor; Value: 0.01uF; U/M: EA; Cap_F: 0.00000001; Tolerance_%: 10; Value1: Unknown; VDC_V: 50; Value2: 50V; TaMin_C: -55; TaMax_C: 125; Cap_Case: 0402; AEC Category: Q200; AEC Qualified: Y; AEC Grade: 1
C234 C238 = CGA2B2C0G1H102J050BA: CAP, CERM, 1000 pF, 50 V, +/- 5%, C0G/NP0, AEC-Q200 Grade 1, 0402; Manufacturer: TDK; Polarized: N; CompType: Capacitor; Value: 1000pF; U/M: EA; Cap_F: 0.000000001; Tolerance_%: 5; Value1: Unknown; VDC_V: 50; Value2: 50V; TaMin_C: -55; TaMax_C: 125; Cap_Case: 0402; AEC Category: Q200; AEC Qualified: Y; AEC Grade: 1
J2 = ARJ012-110553: Connector, RJ-45, R/A, TH; Manufacturer: Abracon Corporation; SymbolCreator: Altium; Pitch_mm: 1.27; Gender: Female; Row_Count: 2; RowSpacing_mm: 2.54; Current_A: 1.5; Voltage_V: 125
J3 = 0-2290024-1: Header(shrouded), 6 Power, 2 Signal, TH; Manufacturer: TE Connectivity; SymbolCreator: Altium; Gender: Male; Shrouded: Y
L3 = DLW43MH201XK2L: Coupled inductor, 200 µH, 4.5 ohm, AEC-Q200 Grade 2, SMD; Manufacturer: MuRata; SymbolCreator: a0412235; SizeAreaWB_mm2: 23.1; SizeArea_mm2: 14.4; SizeX_mm: 3.2; SizeY_mm: 4.5; SizeZ_mm: 2.9; Value: 200uH; Ind_H: 200.0E-6
R2 R9 R18 = RC0201FR-072K49L: RES, 2.49 k, 1%, 0.05 W, 0201; Manufacturer: Yageo America; CompType: Resistor; Value: 2.49k; Res_ohm: 2490; Value_Code: 2k49; Tolerance_%: 1; Power_W: 0.05; Value2: 0.05W; VDC_V: 25; TempCo: 200 ppm/C; SizeArea_mm2: 0.18; SizeX_mm: 0.6; SizeY_mm: 0.3; SizeZ_mm: 0.26; EIA_Code: E96; U/M: EA; AEC Category: Q200; AEC Qualified: N
R11-R14 R17 R20 R136-R143 = CRCW060349R9FKEA: RES, 49.9, 1%, 0.1 W, 0603; Manufacturer: Vishay-Dale; CompType: Resistor; Value: 49.9; Value_Code: 49R9; Tolerance_%: 1; Power_W: 0.1; Value2: 0.1W; VDC_V: 75; TempCo: 100 ppm/C; SizeArea_mm2: 1.28; SizeX_mm: 1.6; SizeY_mm: 0.8; EIA_Code: E96; U/M: EA; AEC Category: Q200
R15 R16 R25 R29 = CRCW02010000Z0ED: RES, 0, 5%, 0.05 W, 0201; Manufacturer: Vishay-Dale; CompType: Resistor; Value: 0; Value_Code: 0000; Tolerance_%: 5; Power_W: 0.05; Value2: 0.05W; TempCo: ppm/C; SizeArea_mm2: 0.18; SizeX_mm: 0.6; SizeY_mm: 0.3; SizeZ_mm: 0.26; EIA_Code: E24; U/M: EA; AEC Category: Q200; AEC Qualified: N
R21 = RC0201FR-074K87L: RES, 4.87 k, 1%, 0.05 W, 0201; Manufacturer: Yageo America; CompType: Resistor; Value: 4.87k; Res_ohm: 4870; Value_Code: 4k87; Tolerance_%: 1; Power_W: 0.05; Value2: 0.05W; VDC_V: 25; TempCo: 200 ppm/C; SizeArea_mm2: 0.18; SizeX_mm: 0.6; SizeY_mm: 0.3; SizeZ_mm: 0.26; EIA_Code: E96; U/M: EA; AEC Category: Q200; AEC Qualified: N
R22 R42 R92 R94 = CRCW040275R0FKED: RES, 75.0, 1%, 0.063 W, 0402; Manufacturer: Vishay-Dale; CompType: Resistor; Value: 75.0; Res_ohm: 75; Value_Code: 75R0; Tolerance_%: 1; Power_W: 0.063; Value2: 0.063W; VDC_V: 50; TempCo: 100 ppm/C; SizeArea_mm2: 0.5; SizeZ_mm: 0.6; EIA_Code: E96; U/M: EA; AEC Category: Q200
R23 R24 = CRCW04020000Z0ED: RES, 0, 5%, 0.063 W, 0402; Manufacturer: Vishay-Dale; CompType: Resistor; Value: 0; Value_Code: 0000; Tolerance_%: 5; Power_W: 0.063; Value2: 0.063W; VDC_V: 50; TempCo: 200 ppm/C; SizeArea_mm2: 0.5; SizeX_mm: 1; SizeZ_mm: 0.6; EIA_Code: E24; U/M: EA; AEC Category: Q200
R26 R27 = ERJ-2RKF2001X: RES, 2.00 k, 1%, 0.1 W, AEC-Q200 Grade 0, 0402; Manufacturer: Panasonic; CompType: Resistor; Value: 2.00k; Res_ohm: 2000; Value_Code: 2k00; Tolerance_%: 1; Power_W: 0.1; Value2: 0.1W; VDC_V: 50; TempCo: 100 ppm/C; SizeArea_mm2: 0.5; SizeZ_mm: 0.6; EIA_Code: E96; U/M: EA; AEC Category: Q200; AEC Qualified: Y; AEC Grade: 0
R28 = CRCW0402100KFKED: RES, 100 k, 1%, 0.063 W, 0402; Manufacturer: Vishay-Dale; CompType: Resistor; Value: 100k; Res_ohm: 100000; Tolerance_%: 1; Power_W: 0.063; Value2: 0.063W; VDC_V: 50; TempCo: 100 ppm/C; SizeArea_mm2: 0.5; SizeZ_mm: 0.6; EIA_Code: E96; U/M: EA; AEC Category: Q200
R34 R35 = RCG060310K0FKEA: RES, 10.0 k, 1%, 0.1 W, 0603; Manufacturer: Vishay Draloric; CompType: Resistor; Value: 10.0k; Res_ohm: 10000; Value_Code: 10k0; Tolerance_%: 1; Power_W: 0.1; Value2: 0.1W; VDC_V: 75; TempCo: 100 ppm/C; SizeArea_mm2: 1.28; SizeX_mm: 1.6; SizeY_mm: 0.8; EIA_Code: E96; U/M: EA; AEC Category: Q200; AEC Qualified: N
R95 = RC1206FR-071ML: RES, 1.00 M, 1%, 0.25 W, 1206; Manufacturer: Yageo America; CompType: Resistor; Value: 1.00Meg; Res_ohm: 1000000; Value_Code: 1M00; Tolerance_%: 1; Power_W: 0.25; Value2: 0.25W; VDC_V: 200; TempCo: 100 ppm/C; SizeArea_mm2: 5.12; SizeX_mm: 3.2; SizeY_mm: 1.6; SizeZ_mm: 1.35; EIA_Code: E96; U/M: EA; AEC Category: Q200
R147 = CRCW04022K49FKED: RES, 2.49 k, 1%, 0.063 W, 0402; Manufacturer: Vishay-Dale; CompType: Resistor; Value: 2.49k; Res_ohm: 2490; Value_Code: 2k49; Tolerance_%: 1; Power_W: 0.063; Value2: 0.063W; VDC_V: 50; TempCo: 100 ppm/C; SizeArea_mm2: 0.5; SizeZ_mm: 0.6; EIA_Code: E96; U/M: EA; AEC Category: Q200
R148 = CRCW06032K49FKEA: RES, 2.49 k, 1%, 0.1 W, 0603; Manufacturer: Vishay-Dale; CompType: Resistor; Value: 2.49k; Res_ohm: 2490; Value_Code: 2k49; Tolerance_%: 1; Power_W: 0.1; Value2: 0.1W; VDC_V: 75; TempCo: 100 ppm/C; SizeArea_mm2: 1.28; SizeX_mm: 1.6; SizeY_mm: 0.8; EIA_Code: E96; U/M: EA; AEC Category: Q200
T1 = HX1188FNLT: Transformer, 350 uH, SMT; Manufacturer: Pulse Engineering; SymbolCreator: Altium; Value: 350uH; Lp: 350
U4 U6-U8 U10 U11 = TPD1E10B06QDPYRQ1: Automotive 1-Channel ESD in 0402 Package With 12pF Capacitance and 6V Breakdown, DPY0002A (X1SON-2); Manufacturer: Texas Instruments; SymbolCreator: a0411947; SizeArea_mm2: 0.6; SizeAreaWB_mm2: 3.2; SizeX_mm: 1; SizeZ_mm: 0.45; CompType: IC; U/M: EA
U5 = DP83848QSQX/NOPB: PHYTER Extended Temperature Single Port 10/100 Mb/s Ethernet Physical Layer Transceiver, RTA0040A (WQFN-40); Alternate PartNumber: DP83848QSQ/NOPB; Manufacturer: Texas Instruments; SymbolCreator: Altium; SizeArea_mm2: 36; SizeAreaWB_mm2: 64; SizeX_mm: 6; SizeZ_mm: 0.8; CompType: IC; U/M: EA
U9 = DP83TC811RND: DP83TC811,RND0036A; Manufacturer: Texas Instruments; SymbolCreator: Altium; SizeArea_mm2: 36; SizeAreaWB_mm2: 64; SizeX_mm: 6; SizeZ_mm: 0.9; CompType: IC; U/M: EA

## Sheet CAN_subsystem2.0.SchDoc: CAN_subsystem2.0
size 431 x 279 mm; Date: Not shown in title block; ApprovedBy: Not shown in title block; CheckedBy: Not shown in title block; Author: Not shown in title block; CompanyName: Not shown in title block; DrawnBy: Donovan Porter; Engineer: Not shown in title block; Organization: Not shown in title block; Address1: Not shown in title block; Address2: Not shown in title block; Address3: Not shown in title block; Address4: Not shown in title block; DocumentNumber: 8; Revision: Use project parameter SCH_Rev; SheetNumber: 8; SheetTotal: 12; PageSetup: Record=PageOptions¦CenterHorizontal=True¦CenterVertical=True¦PrintScale=1.00¦XCorrection=1.00¦YCorrection=1.00¦PrintKind=0¦BorderSize=5000000¦LeftOffset=0¦BottomOffset=0¦Orientation=2¦PaperLength=1000¦PaperWidth=1000¦Scale=100¦PaperSource=15¦PrintQuality=600¦MediaType=1¦DitherType=10¦PaperKind=Letter¦PrintScaleMode=1
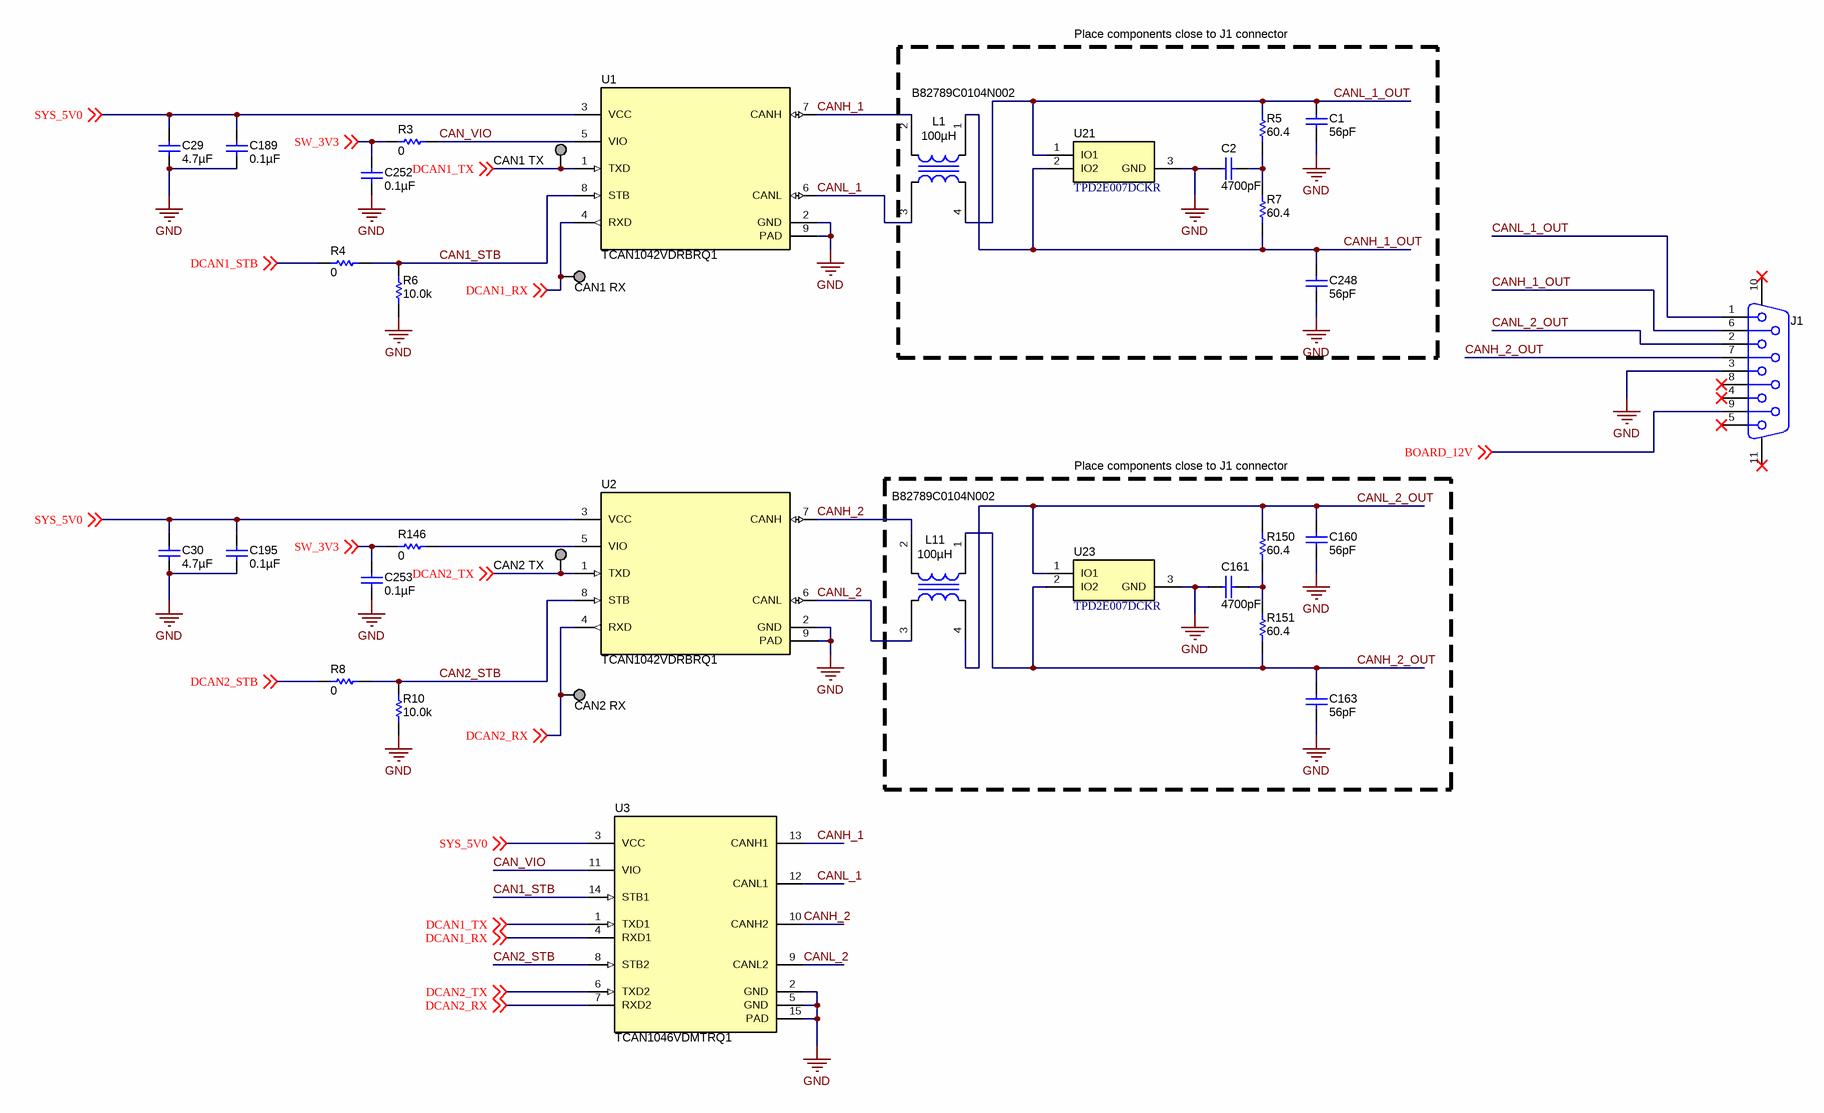
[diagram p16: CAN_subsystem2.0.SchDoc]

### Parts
C1  ValueDisplayed: 56pF  [0603]  (hidden comment: GRM1885C1H560JA01D)
C2  ValueDisplayed: 4700pF  [0603]  (hidden comment: GCM188R71H472KA37D)
C29  ValueDisplayed: 4.7µF  [0805_HV]  (hidden comment: C2012X7R1A475M125AC)
C30  ValueDisplayed: 4.7µF  [0805_HV]  (hidden comment: C2012X7R1A475M125AC)
C160  ValueDisplayed: 56pF  [0603]  (hidden comment: GRM1885C1H560JA01D)
C161  ValueDisplayed: 4700pF  [0603]  (hidden comment: GCM188R71H472KA37D)
C163  ValueDisplayed: 56pF  [0603]  (hidden comment: GRM1885C1H560JA01D)
C189  ValueDisplayed: 0.1µF  [0402]  (hidden comment: GRM155R71C104KA88D)
C195  ValueDisplayed: 0.1µF  [0402]  (hidden comment: GRM155R71C104KA88D)
C248  ValueDisplayed: 56pF  [0603]  (hidden comment: GRM1885C1H560JA01D)
C252  ValueDisplayed: 0.1µF  [0603]  (hidden comment: 06033C104JAT2A)
C253  ValueDisplayed: 0.1µF  [0603]  (hidden comment: 06033C104JAT2A)
CAN1_RX  TESTPOINT  [PAD_2-92x0-9MM_SMD]  (value not drawn)  (no BOM)
CAN1_TX  TESTPOINT  [PAD_2-92x0-9MM_SMD]  (value not drawn)  (no BOM)
CAN2_RX  TESTPOINT  [PAD_2-92x0-9MM_SMD]  (value not drawn)  (no BOM)
CAN2_TX  TESTPOINT  [PAD_2-92x0-9MM_SMD]  (value not drawn)  (no BOM)
J1  1734354-1  [TE_1734354-1]  (value not drawn)
L1  B82789C0104N002  ValueDisplayed: 100µH  [SIMDAD_1812]
L11  B82789C0104N002  ValueDisplayed: 100µH  [SIMDAD_1812]
R3  ValueDisplayed: 0  [0201]  (hidden comment: CRCW02010000Z0ED)
R4  ValueDisplayed: 0  [0603]  (hidden comment: ERJ-3GEY0R00V)
R5  ValueDisplayed: 60.4  [1206]  (hidden comment: CRCW120660R4FKEA)
R6  ValueDisplayed: 10.0k  [0603]  (hidden comment: RCG060310K0FKEA)
R7  ValueDisplayed: 60.4  [1206]  (hidden comment: CRCW120660R4FKEA)
R8  ValueDisplayed: 0  [0603]  (hidden comment: ERJ-3GEY0R00V)
R10  ValueDisplayed: 10.0k  [0603]  (hidden comment: RCG060310K0FKEA)
R146  ValueDisplayed: 0  [0201]  (hidden comment: CRCW02010000Z0ED)
R150  ValueDisplayed: 60.4  [1206]  (hidden comment: CRCW120660R4FKEA)
R151  ValueDisplayed: 60.4  [1206]  (hidden comment: CRCW120660R4FKEA)
U1  TCAN1042VDRBRQ1  [DRB0008F]
U2  TCAN1042VDRBRQ1  [DRB0008F]
U3  TCAN1046VDMTRQ1  [DMT0014A]
U21  TPD2E007DCKR  [DCK0003A_N]
U23  TPD2E007DCKR  [DCK0003A_N]

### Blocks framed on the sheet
Place components close to J1 connector: C1 C2 C248 L1 R5 R7 U21
Place components close to J1 connector: C160 C161 C163 L11 R150 R151 U23

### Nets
GND: C1.2 C2.2 C29.2 C30.2 C160.2 C161.2 C163.2 C189.2 C195.2 C248.2 C252.2 C253.2 J1.3 R6.1 R10.1 U1.2(GND) U1.9(PAD) U2.2(GND) U2.9(PAD) U3.2(GND) U3.5(GND) U3.15(PAD) U21.3(GND) U23.3(GND)
BOARD_12V: J1.9 ; off-sheet BOARD_12V
CAN1_STB: R4.1 R6.2 U1.8(STB) U3.14(STB1)
CAN2_STB: R8.1 R10.2 U2.8(STB) U3.8(STB2)
CAN_VIO: R3.1 U1.5(VIO) U3.11(VIO)
CANH_1: L1.2 U1.7(CANH) U3.13(CANH1)
CANH_1_OUT: C248.1 J1.6 L1.1 R7.1 U21.2(IO2)
CANH_2: L11.2 U2.7(CANH) U3.10(CANH2)
CANH_2_OUT: C163.1 J1.7 L11.1 R151.1 U23.2(IO2)
CANL_1: L1.3 U1.6(CANL) U3.12(CANL1)
CANL_1_OUT: C1.1 J1.1 L1.4 R5.2 U21.1(IO1)
CANL_2: L11.3 U2.6(CANL) U3.9(CANL2)
CANL_2_OUT: C160.1 J1.2 L11.4 R150.2 U23.1(IO1)
DCAN1_RX: CAN1_RX.1 U1.4(RXD) U3.4(RXD1) ; off-sheet DCAN1_RX
DCAN1_STB: R4.2 ; off-sheet DCAN1_STB
DCAN1_TX: CAN1_TX.1 U1.1(TXD) U3.1(TXD1) ; off-sheet DCAN1_TX
DCAN2_RX: CAN2_RX.1 U2.4(RXD) U3.7(RXD2) ; off-sheet DCAN2_RX
DCAN2_STB: R8.2 ; off-sheet DCAN2_STB
DCAN2_TX: CAN2_TX.1 U2.1(TXD) U3.6(TXD2) ; off-sheet DCAN2_TX
SW_3V3: C252.1 C253.1 R3.2 R146.2 ; off-sheet SW_3V3
SYS_5V0: C29.1 C30.1 C189.1 C195.1 U1.3(VCC) U2.3(VCC) U3.3(VCC) ; off-sheet SYS_5V0
NetC2_1: C2.1 R5.1 R7.2
NetC161_1: C161.1 R150.1 R151.2
NetR146_1: R146.1 U2.5(VIO)

Not connected (* = marked no-connect by the designer): J1 4* 5* 8* 10* 11*

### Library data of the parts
C1 C160 C163 C248 = GRM1885C1H560JA01D: CAP, CERM, 56 pF, 50 V, +/- 5%, C0G/NP0, 0603; Manufacturer: MuRata; Polarized: N; CompType: Capacitor; Value: 56pF; U/M: EA; Cap_F: 0.000000000056; Tolerance_%: 5; Value1: Unknown; VDC_V: 50; Value2: 50V; TaMin_C: -55; TaMax_C: 125; SizeArea_mm2: 1.28; SizeAreaWB_mm2: 4.68; SizeX_mm: 1.6; SizeY_mm: 0.8; SizeZ_mm: 1; AEC Category: Q200
C2 C161 = GCM188R71H472KA37D: CAP, CERM, 4700 pF, 50 V, +/- 10%, X7R, AEC-Q200 Grade 1, 0603; Manufacturer: MuRata; Polarized: N; CompType: Capacitor; Value: 4700pF; U/M: EA; Cap_F: 0.0000000047; Tolerance_%: 10; Value1: Unknown; VDC_V: 50; Value2: 50V; TaMin_C: -55; TaMax_C: 125; SizeArea_mm2: 1.28; SizeAreaWB_mm2: 4.68; SizeX_mm: 1.6; SizeY_mm: 0.8; SizeZ_mm: 1; AEC Category: Q200; AEC Qualified: Y
C29 C30 = C2012X7R1A475M125AC: CAP, CERM, 4.7 µF, 10 V, +/- 20%, X7R, 0805; Manufacturer: TDK; Polarized: N; CompType: Capacitor; Value: 4.7uF; U/M: EA; Cap_F: 0.0000047; Tolerance_%: 20; Value1: Unknown; VDC_V: 10; Value2: 10V; TaMin_C: -55; TaMax_C: 125; Cap_Case: 0805; SizeArea_mm2: 2.5; SizeAreaWB_mm2: 6.75; SizeX_mm: 2; SizeY_mm: 1.25; SizeZ_mm: 1.45; AEC Category: Q200
C189 C195 = GRM155R71C104KA88D: CAP, CERM, 0.1 µF, 16 V, +/- 10%, X7R, 0402; Manufacturer: MuRata; Polarized: N; CompType: Capacitor; Value: 0.1uF; U/M: EA; Cap_F: 0.0000001; Tolerance_%: 10; Value1: Unknown; VDC_V: 16; Value2: 16V; TaMin_C: -55; TaMax_C: 125; SizeArea_mm2: 0.5; SizeAreaWB_mm2: 3; SizeX_mm: 1; SizeZ_mm: 0.6; AEC Category: Q200
C252 C253 = 06033C104JAT2A: CAP, CERM, 0.1 µF, 25 V, +/- 5%, X7R, 0603; Manufacturer: AVX; Polarized: N; CompType: Capacitor; Value: 0.1uF; U/M: EA; Cap_F: 0.0000001; Tolerance_%: 5; ESR_ohm: 0.05; Value1: 0.05 ohm; VDC_V: 25; Value2: 25V; TaMin_C: -55; TaMax_C: 125; SizeArea_mm2: 1.28; SizeAreaWB_mm2: 4.68; SizeX_mm: 1.6; SizeY_mm: 0.8; SizeZ_mm: 1; AEC Category: Q200
CAN1_RX CAN1_TX CAN2_RX CAN2_TX = PAD_2.92x0.9MM_SMD: 2.92x0.9mm Pad, SMD; Manufacturer: Any
J1 = 1734354-1: Receptacle, D-Sub, 9 Position, R/A, TH; Manufacturer: TE Connectivity; SymbolCreator: Altium; Gender: Female; ContactFinish: Gold
L1 L11 = B82789C0104N002: Coupled inductor, 100 µH, 0.15 A, 1.5 ohm, SMD; Manufacturer: TDK; SymbolCreator: Altium; Value: 100uH; Ind_H: 100.0E-6; DCR_ohm: 1.5
R3 R146 = CRCW02010000Z0ED: as R15 on sheet Ethernet_subsystem
R4 R8 = ERJ-3GEY0R00V: RES, 0, 5%, 0.1 W, 0603; Manufacturer: Panasonic; CompType: Resistor; Value: 0; Value_Code: 0000; Tolerance_%: 5; Power_W: 0.1; Value2: 0.1W; VDC_V: 50; TempCo: 600 ppm/C; SizeArea_mm2: 1.28; SizeX_mm: 1.6; SizeY_mm: 0.8; SizeZ_mm: 1; EIA_Code: E24; U/M: EA; AEC Category: Q200
R5 R7 R150 R151 = CRCW120660R4FKEA: RES, 60.4, 1%, 0.25 W, 1206; Manufacturer: Vishay-Dale; CompType: Resistor; Value: 60.4; Value_Code: 60R4; Tolerance_%: 1; Power_W: 0.25; Value2: 0.25W; VDC_V: 200; TempCo: 100 ppm/C; SizeArea_mm2: 5.12; SizeX_mm: 3.2; SizeY_mm: 1.6; SizeZ_mm: 1.35; EIA_Code: E96; U/M: EA; AEC Category: Q200
R6 R10 = RCG060310K0FKEA: as R34 on sheet Ethernet_subsystem
U1 U2 = TCAN1042VDRBRQ1: Automotive Fault Protected CAN Transceiver With Flexible Data-Rate, DRB0008F (VSON-8); Alternate PartNumber: TCAN1042VDRBTQ1; Manufacturer: Texas Instruments; SymbolCreator: a0411947; SizeArea_mm2: 9; SizeAreaWB_mm2: 16; SizeX_mm: 3; SizeZ_mm: 1; CompType: IC; U/M: EA
U3 = TCAN1046VDMTRQ1: Automotive High Speed Dual CAN Transceiver, DMT0014A (VSON-14); Manufacturer: Texas Instruments; SymbolCreator: a0411947; SizeArea_mm2: 13.5; SizeAreaWB_mm2: 22; SizeX_mm: 3; SizeY_mm: 4.5; SizeZ_mm: 0.9; CompType: IC; U/M: EA
U21 U23 = TPD2E007DCKR: ESD Protection Array for AC Signal Data Interface, 2 Channels, -40 to +85 degC, 3-pin SC70 (DCK), Green (RoHS & no Sb/Br); Manufacturer: Texas Instruments; Alternate PartNumber: Equivalent; Breakdown Voltage(Min)(V): +/-14; IEC 61000-4-2 Air-Gap(+/- kV): 15; IEC 61000-4-2 Contact(+/- kV): 8; IO Leakage Current(nA): 50; SubFamily: ESD Solution

## Sheet JTAG.SchDoc: JTAG
size 431 x 279 mm; Date: Not shown in title block; ApprovedBy: Not shown in title block; CheckedBy: Not shown in title block; Author: Not shown in title block; CompanyName: Not shown in title block; DrawnBy: Donovan Porter; Engineer: Not shown in title block; Organization: Not shown in title block; Address1: Not shown in title block; Address2: Not shown in title block; Address3: Not shown in title block; Address4: Not shown in title block; DocumentNumber: 11; Revision: Use project parameter SCH_Rev; SheetNumber: 11; SheetTotal: 12; PageSetup: Record=PageOptions¦CenterHorizontal=True¦CenterVertical=True¦PrintScale=1.00¦XCorrection=1.00¦YCorrection=1.00¦PrintKind=0¦BorderSize=5000000¦LeftOffset=0¦BottomOffset=0¦Orientation=2¦PaperLength=1000¦PaperWidth=1000¦Scale=100¦PaperSource=15¦PrintQuality=600¦MediaType=1¦DitherType=10¦PaperKind=Letter¦PrintScaleMode=1
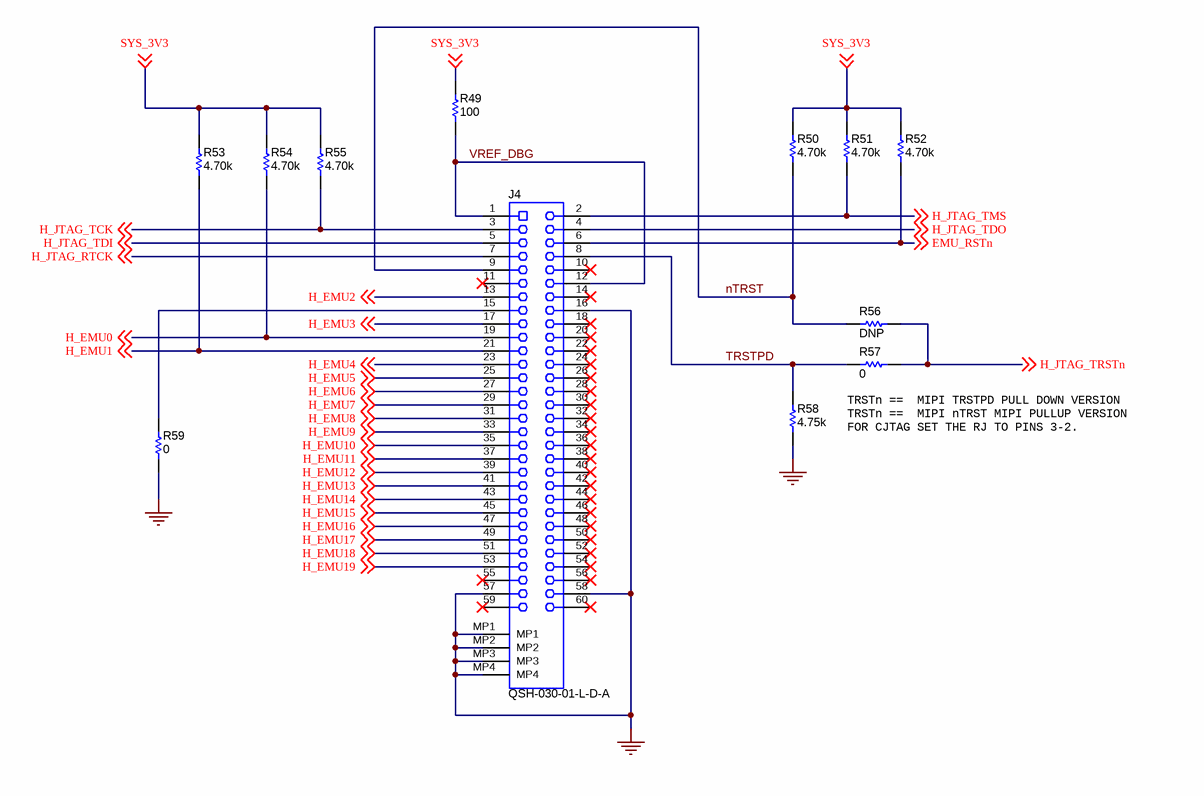
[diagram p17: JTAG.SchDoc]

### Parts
J4  QSH-030-01-L-D-A  [Samtec_QSH-030-01-X-D-A]
R49  ValueDisplayed: 100  [0402]  (hidden comment: MCR01MZPF1000)
R50  ValueDisplayed: 4.70k  [0402]  (hidden comment: CRG0402F4K7)
R51  ValueDisplayed: 4.70k  [0402]  (hidden comment: CRG0402F4K7)
R52  ValueDisplayed: 4.70k  [0402]  (hidden comment: CRG0402F4K7)
R53  ValueDisplayed: 4.70k  [0402]  (hidden comment: CRG0402F4K7)
R54  ValueDisplayed: 4.70k  [0402]  (hidden comment: CRG0402F4K7)
R55  ValueDisplayed: 4.70k  [0402]  (hidden comment: CRG0402F4K7)
R56  ValueDisplayed: DNP  [0201]  (hidden comment: CRCW02010000Z0ED)
R57  ValueDisplayed: 0  [0201]  (hidden comment: CRCW02010000Z0ED)
R58  ValueDisplayed: 4.75k  [0805_HV]  (hidden comment: CRCW08054K75FKEA)
R59  ValueDisplayed: 0  [0201]  (hidden comment: CRCW02010000Z0ED)

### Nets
GND: J4.16 J4.57 J4.58 J4.MP1 J4.MP2 J4.MP3 J4.MP4 R58.1 R59.1
EMU_RSTn: J4.6 R52.1 ; off-sheet EMU_RSTn
H_EMU0: J4.19 R54.1 ; off-sheet H_EMU0
H_EMU1: J4.21 R53.1 ; off-sheet H_EMU1
H_EMU2: J4.13 ; off-sheet H_EMU2
H_EMU3: J4.17 ; off-sheet H_EMU3
H_EMU4: J4.23 ; off-sheet H_EMU4
H_EMU5: J4.25 ; off-sheet H_EMU5
H_EMU6: J4.27 ; off-sheet H_EMU6
H_EMU7: J4.29 ; off-sheet H_EMU7
H_EMU8: J4.31 ; off-sheet H_EMU8
H_EMU9: J4.33 ; off-sheet H_EMU9
H_EMU10: J4.35 ; off-sheet H_EMU10
H_EMU11: J4.37 ; off-sheet H_EMU11
H_EMU12: J4.39 ; off-sheet H_EMU12
H_EMU13: J4.41 ; off-sheet H_EMU13
H_EMU14: J4.43 ; off-sheet H_EMU14
H_EMU15: J4.45 ; off-sheet H_EMU15
H_EMU16: J4.47 ; off-sheet H_EMU16
H_EMU17: J4.49 ; off-sheet H_EMU17
H_EMU18: J4.51 ; off-sheet H_EMU18
H_EMU19: J4.53 ; off-sheet H_EMU19
H_JTAG_RTCK: J4.7 ; off-sheet H_JTAG_RTCK
H_JTAG_TCK: J4.3 R55.1 ; off-sheet H_JTAG_TCK
H_JTAG_TDI: J4.5 ; off-sheet H_JTAG_TDI
H_JTAG_TDO: J4.4 ; off-sheet H_JTAG_TDO
H_JTAG_TMS: J4.2 R51.1 ; off-sheet H_JTAG_TMS
H_JTAG_TRSTn: R56.1 R57.1 ; off-sheet H_JTAG_TRSTn
nTRST: J4.9 R50.1 R56.2
SYS_3V3: R49.2 R50.2 R51.2 R52.2 R53.2 R54.2 R55.2 ; off-sheet SYS_3V3
TRSTPD: J4.8 R57.2 R58.2
VREF_DBG: J4.1 J4.12 R49.1
NetJ4_15: J4.15 R59.2

Not connected (* = marked no-connect by the designer): J4 10* 11* 14* 18* 20* 22* 24* 26* 28* 30* 32* 34* 36* 38* 40* 42* 44* 46* 48* 50* 52* 54* 55* 56* 59* 60*

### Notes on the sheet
- (near R57) TRSTn ==  MIPI TRSTPD PULL DOWN VERSION
  TRSTn ==  MIPI nTRST MIPI PULLUP VERSION
  FOR CJTAG SET THE RJ TO PINS 3-2.

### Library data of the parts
J4 = QSH-030-01-L-D-A: Receptacle, 0.5 mm, 30x2, Gold, TH; Manufacturer: Samtec; SymbolCreator: Altium; Pitch_mm: 0.5; Gender: Female; Shrouded: N; Row_Count: 2; RowSpacing_mm: 5.73
R49 = MCR01MZPF1000: RES, 100, 1%, 0.063 W, 0402; Manufacturer: Rohm; CompType: Resistor; Value: 100; Value_Code: 100R; Tolerance_%: 1; Power_W: 0.063; Value2: 0.063W; VDC_V: 50; TempCo: 100 ppm/C; SizeArea_mm2: 0.5; SizeZ_mm: 0.6; EIA_Code: E96; U/M: EA; AEC Category: Q200; AEC Qualified: N
R50-R55 = CRG0402F4K7: RES, 4.70 k, 1%, 0.063 W, 0402; Manufacturer: TE Connectivity; CompType: Resistor; Value: 4.70k; Res_ohm: 4700; Value_Code: 4k70; Tolerance_%: 1; Power_W: 0.063; Value2: 0.063W; TempCo: 100 ppm/C; SizeArea_mm2: 0.5; SizeZ_mm: 0.6; U/M: EA; AEC Category: Q200; AEC Qualified: N
R56 R57 R59 = CRCW02010000Z0ED: as R15 on sheet Ethernet_subsystem
R58 = CRCW08054K75FKEA: RES, 4.75 k, 1%, 0.125 W, 0805; Manufacturer: Vishay-Dale; CompType: Resistor; Value: 4.75k; Res_ohm: 4750; Value_Code: 4k75; Tolerance_%: 1; Power_W: 0.125; Value2: 0.125W; VDC_V: 150; TempCo: 100 ppm/C; SizeArea_mm2: 2.5; SizeX_mm: 2; SizeY_mm: 1.25; SizeZ_mm: 1.45; EIA_Code: E96; U/M: EA; AEC Category: Q200

## Sheet TIDA-01425_EVM_Hardware.SchDoc: Hardware
size 431 x 279 mm; Date: Not shown in title block; ApprovedBy: Not shown in title block; CheckedBy: Not shown in title block; Author: Not shown in title block; CompanyName: Not shown in title block; DrawnBy: Donovan Porter; Engineer: Not shown in title block; Organization: Not shown in title block; Address1: Not shown in title block; Address2: Not shown in title block; Address3: Not shown in title block; Address4: Not shown in title block; DocumentNumber: 12; Revision: Use project parameter SCH_Rev; SheetNumber: 12; SheetTotal: 12; PageSetup: Record=PageOptions¦CenterHorizontal=True¦CenterVertical=True¦PrintScale=1.00¦XCorrection=1.00¦YCorrection=1.00¦PrintKind=0¦BorderSize=5000000¦LeftOffset=0¦BottomOffset=0¦Orientation=2¦PaperLength=1000¦PaperWidth=1000¦Scale=100¦PaperSource=15¦PrintQuality=600¦MediaType=1¦DitherType=10¦PaperKind=Letter¦PrintScaleMode=1
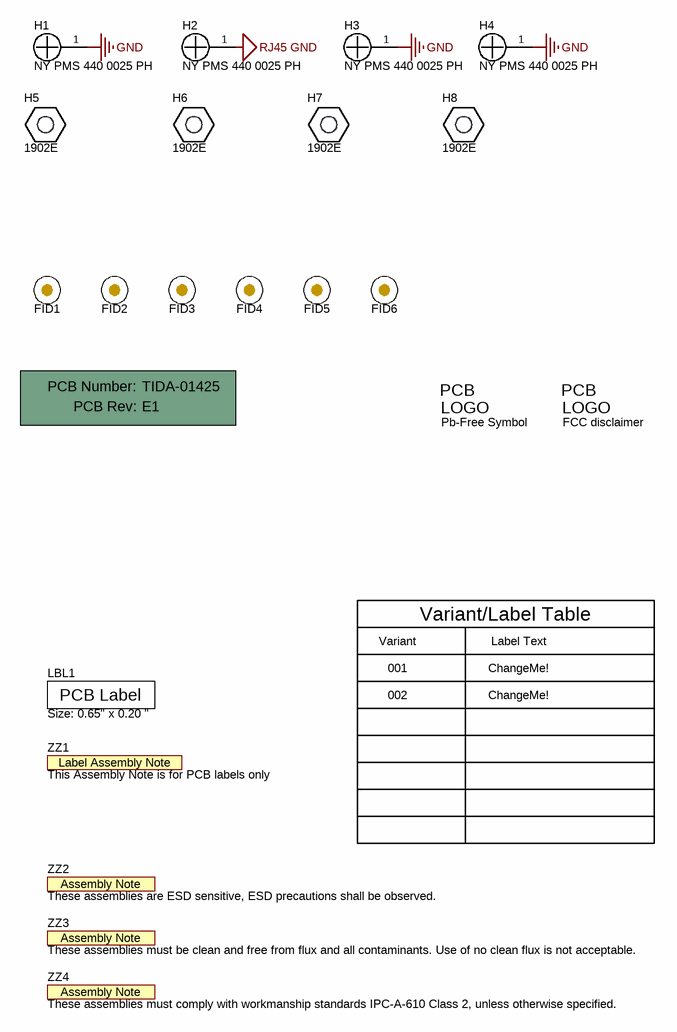
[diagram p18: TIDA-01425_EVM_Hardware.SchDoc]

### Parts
!PCB1  Printed Circuit Board  (value not drawn)  (mechanical)
FID1  Fiducial  [Fiducial10-20]  (value not drawn)
FID2  Fiducial  [Fiducial10-20]  (value not drawn)
FID3  Fiducial  [Fiducial10-20]  (value not drawn)
FID4  Fiducial  [Fiducial10-20]  (value not drawn)
FID5  Fiducial  [Fiducial10-20]  (value not drawn)
FID6  Fiducial  [Fiducial10-20]  (value not drawn)
H1  NY PMS 440 0025 PH  [NY PMS 440 0025 PH]
H2  NY PMS 440 0025 PH  [NY PMS 440 0025 PH]
H3  NY PMS 440 0025 PH  [NY PMS 440 0025 PH]
H4  NY PMS 440 0025 PH  [NY PMS 440 0025 PH]
H5  1902E  [Keystone_1902E]
H6  1902E  [Keystone_1902E]
H7  1902E  [Keystone_1902E]
H8  1902E  [Keystone_1902E]
LBL1  Size: 0.65" x 0.20 "  [Label_650x200]
Logo2  Pb-Free Symbol  [Pb-Free_Overlay_Small]  (no BOM)
Logo3  FCC disclaimer  [FCC_disclaimer]  (no BOM)
ZZ1  This Assembly Note is for PCB labels only  [AssemblyNoteLabel]  (no BOM)
ZZ2  These assemblies are ESD sensitive, ESD precautions shall be observed.  [AssemblyNote]  (no BOM)
ZZ3  These assemblies must be clean and free from flux and all contaminants. Use of no clean flux is not acceptable.  [AssemblyNote]  (no BOM)
ZZ4  These assemblies must comply with workmanship standards IPC-A-610 Class 2, unless otherwise specified.  [AssemblyNote]  (no BOM)

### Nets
GND: H1.1 H3.1 H4.1
RJ45 GND: H2.1

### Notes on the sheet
- Variant
- Variant/Label Table
- Label Text
- 001
- 002
- ChangeMe!

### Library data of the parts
!PCB1 = PCB: Manufacturer: Any; PartNumber: TIDA-01425; SymbolCreator: a0412235
FID1-FID6 = Fiducial: Fiducial mark.  There is nothing to buy or mount.; SymbolCreator: codlsc
H1-H4 = NY PMS 440 0025 PH: Machine Screw, Round, #4-40 x 1/4, Nylon, Philips panhead; Manufacturer: B&F Fastener Supply; CompType: Hardware; SymbolCreator: codlsc; U/M: EA
H5-H8 = 1902E: Standoff, Hex, 1"L #4-40 Nylon; Manufacturer: Keystone; SymbolCreator: a0412235; CompType: Hardware
LBL1 = THT-14-423-10: Thermal Transfer Printable Labels, 0.650" W x 0.200" H - 10,000 per roll; Manufacturer: Brady; SymbolCreator: a0412235; CompType: Label
Logo2 = Pb-Free: SymbolCreator: a0412235
Logo3 = FCC_disclaimer: SymbolCreator: codlsc
ZZ1 = AssemblyNoteLabel: SymbolCreator: a0412235
ZZ2-ZZ4 = AssemblyNote: SymbolCreator: codlsc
